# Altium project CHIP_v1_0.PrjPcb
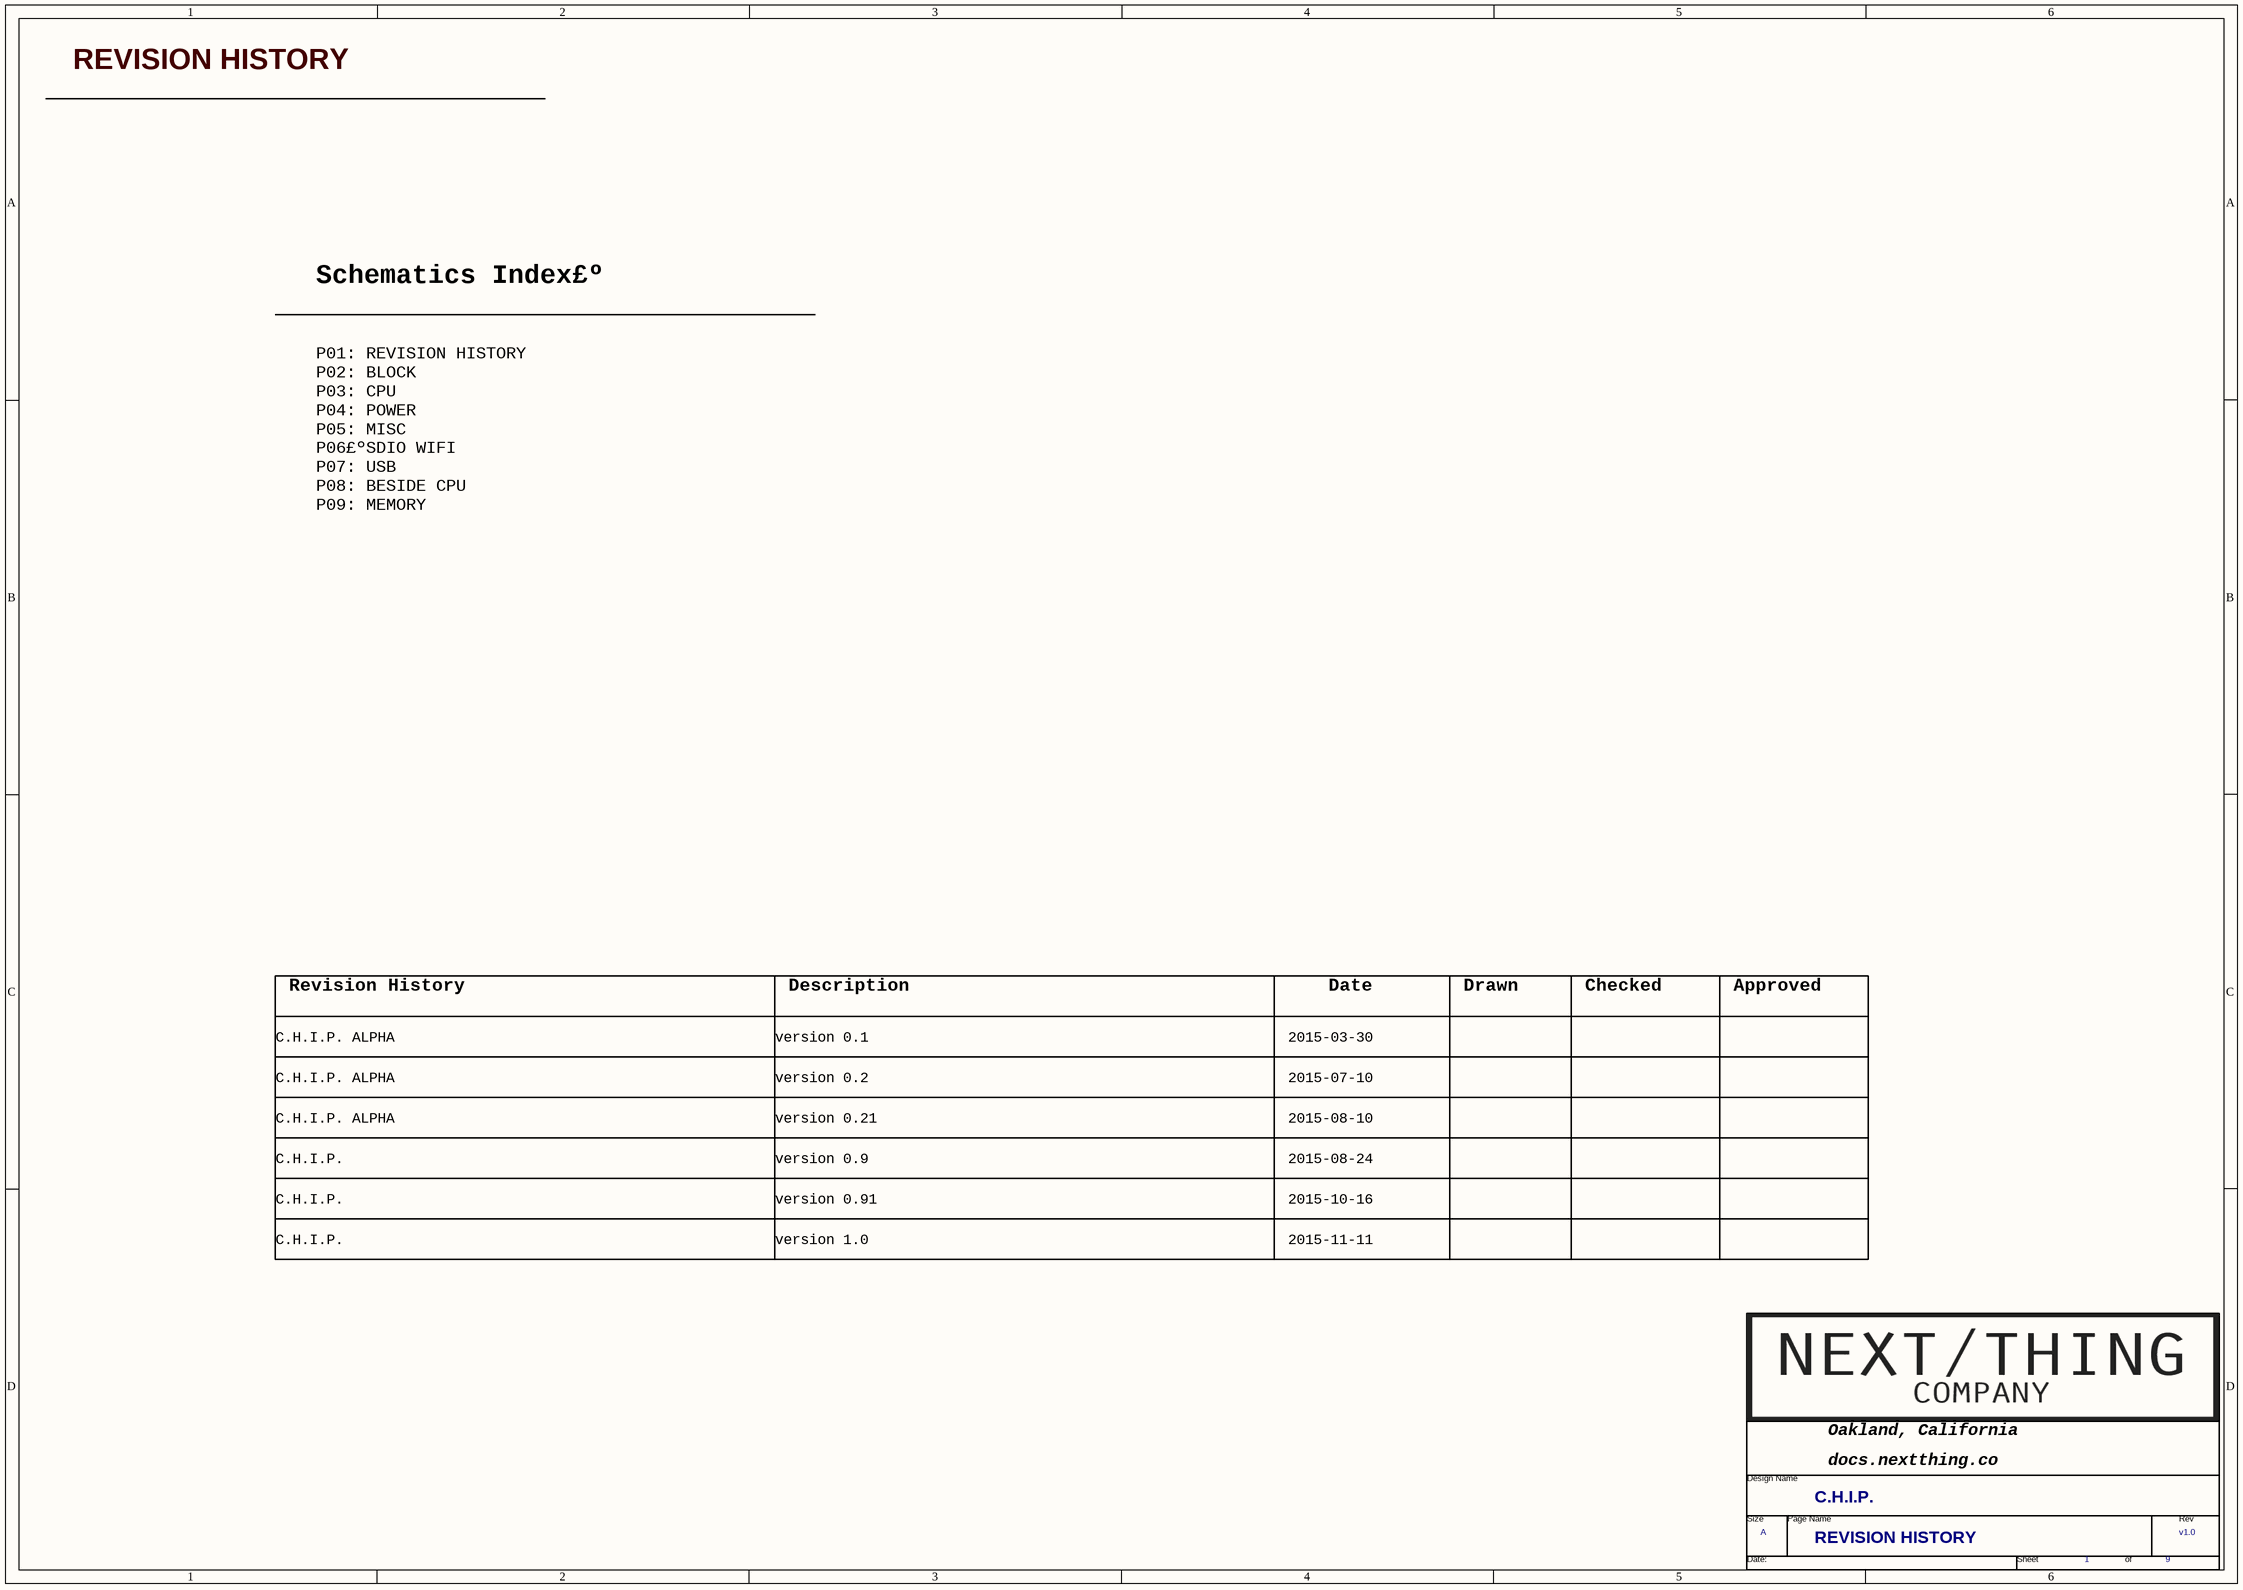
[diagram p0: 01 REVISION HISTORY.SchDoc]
9 sheets, 288 parts. Net scope: global (net labels, ports and power ports of the same name join across sheets).
Sheets:
  01 REVISION HISTORY.SchDoc
  02 BLOCK.SchDoc
  03 CPU.SchDoc
  04 POWER.SchDoc
  05 MISC.SchDoc
  06 SDIO WIFI&BT.SchDoc
  07 USB.SchDoc
  08 BESIDE CPU.SchDoc
  09 DDR3.SchDoc

## Sheet 01 REVISION HISTORY.SchDoc
size 420 x 297 mm

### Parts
(Parts that share a designator on the sheet are numbered #1, #2 ... from top to bottom, then left to right.)
*#1  Page Count: 9  Page Number: 1  Page Size: A  Title: C.H.I.P.  RevCode: v1.0  Doc: REVISION HISTORY  (hidden comment: TitleBlock1-nextthing)  (graphical)

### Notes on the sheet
- REVISION HISTORY
- Schematics Index£º
- P01: REVISION HISTORY
  P02: BLOCK
  P03: CPU
  P04: POWER
  P05: MISC
  P06£ºSDIO WIFI
  P07: USB
  P08: BESIDE CPU
  P09: MEMORY
- Revision History
- Description
- Date
- Drawn
- Checked
- Approved
- C.H.I.P. ALPHA
- version 0.1
- 2015-03-30
- version 0.2
- version 0.21
- 2015-07-10
- 2015-08-10
- C.H.I.P.
- version 0.9
- version 0.91
- 2015-08-24
- 2015-10-16
- version 1.0
- 2015-11-11

## Sheet 02 BLOCK.SchDoc
size 420 x 297 mm
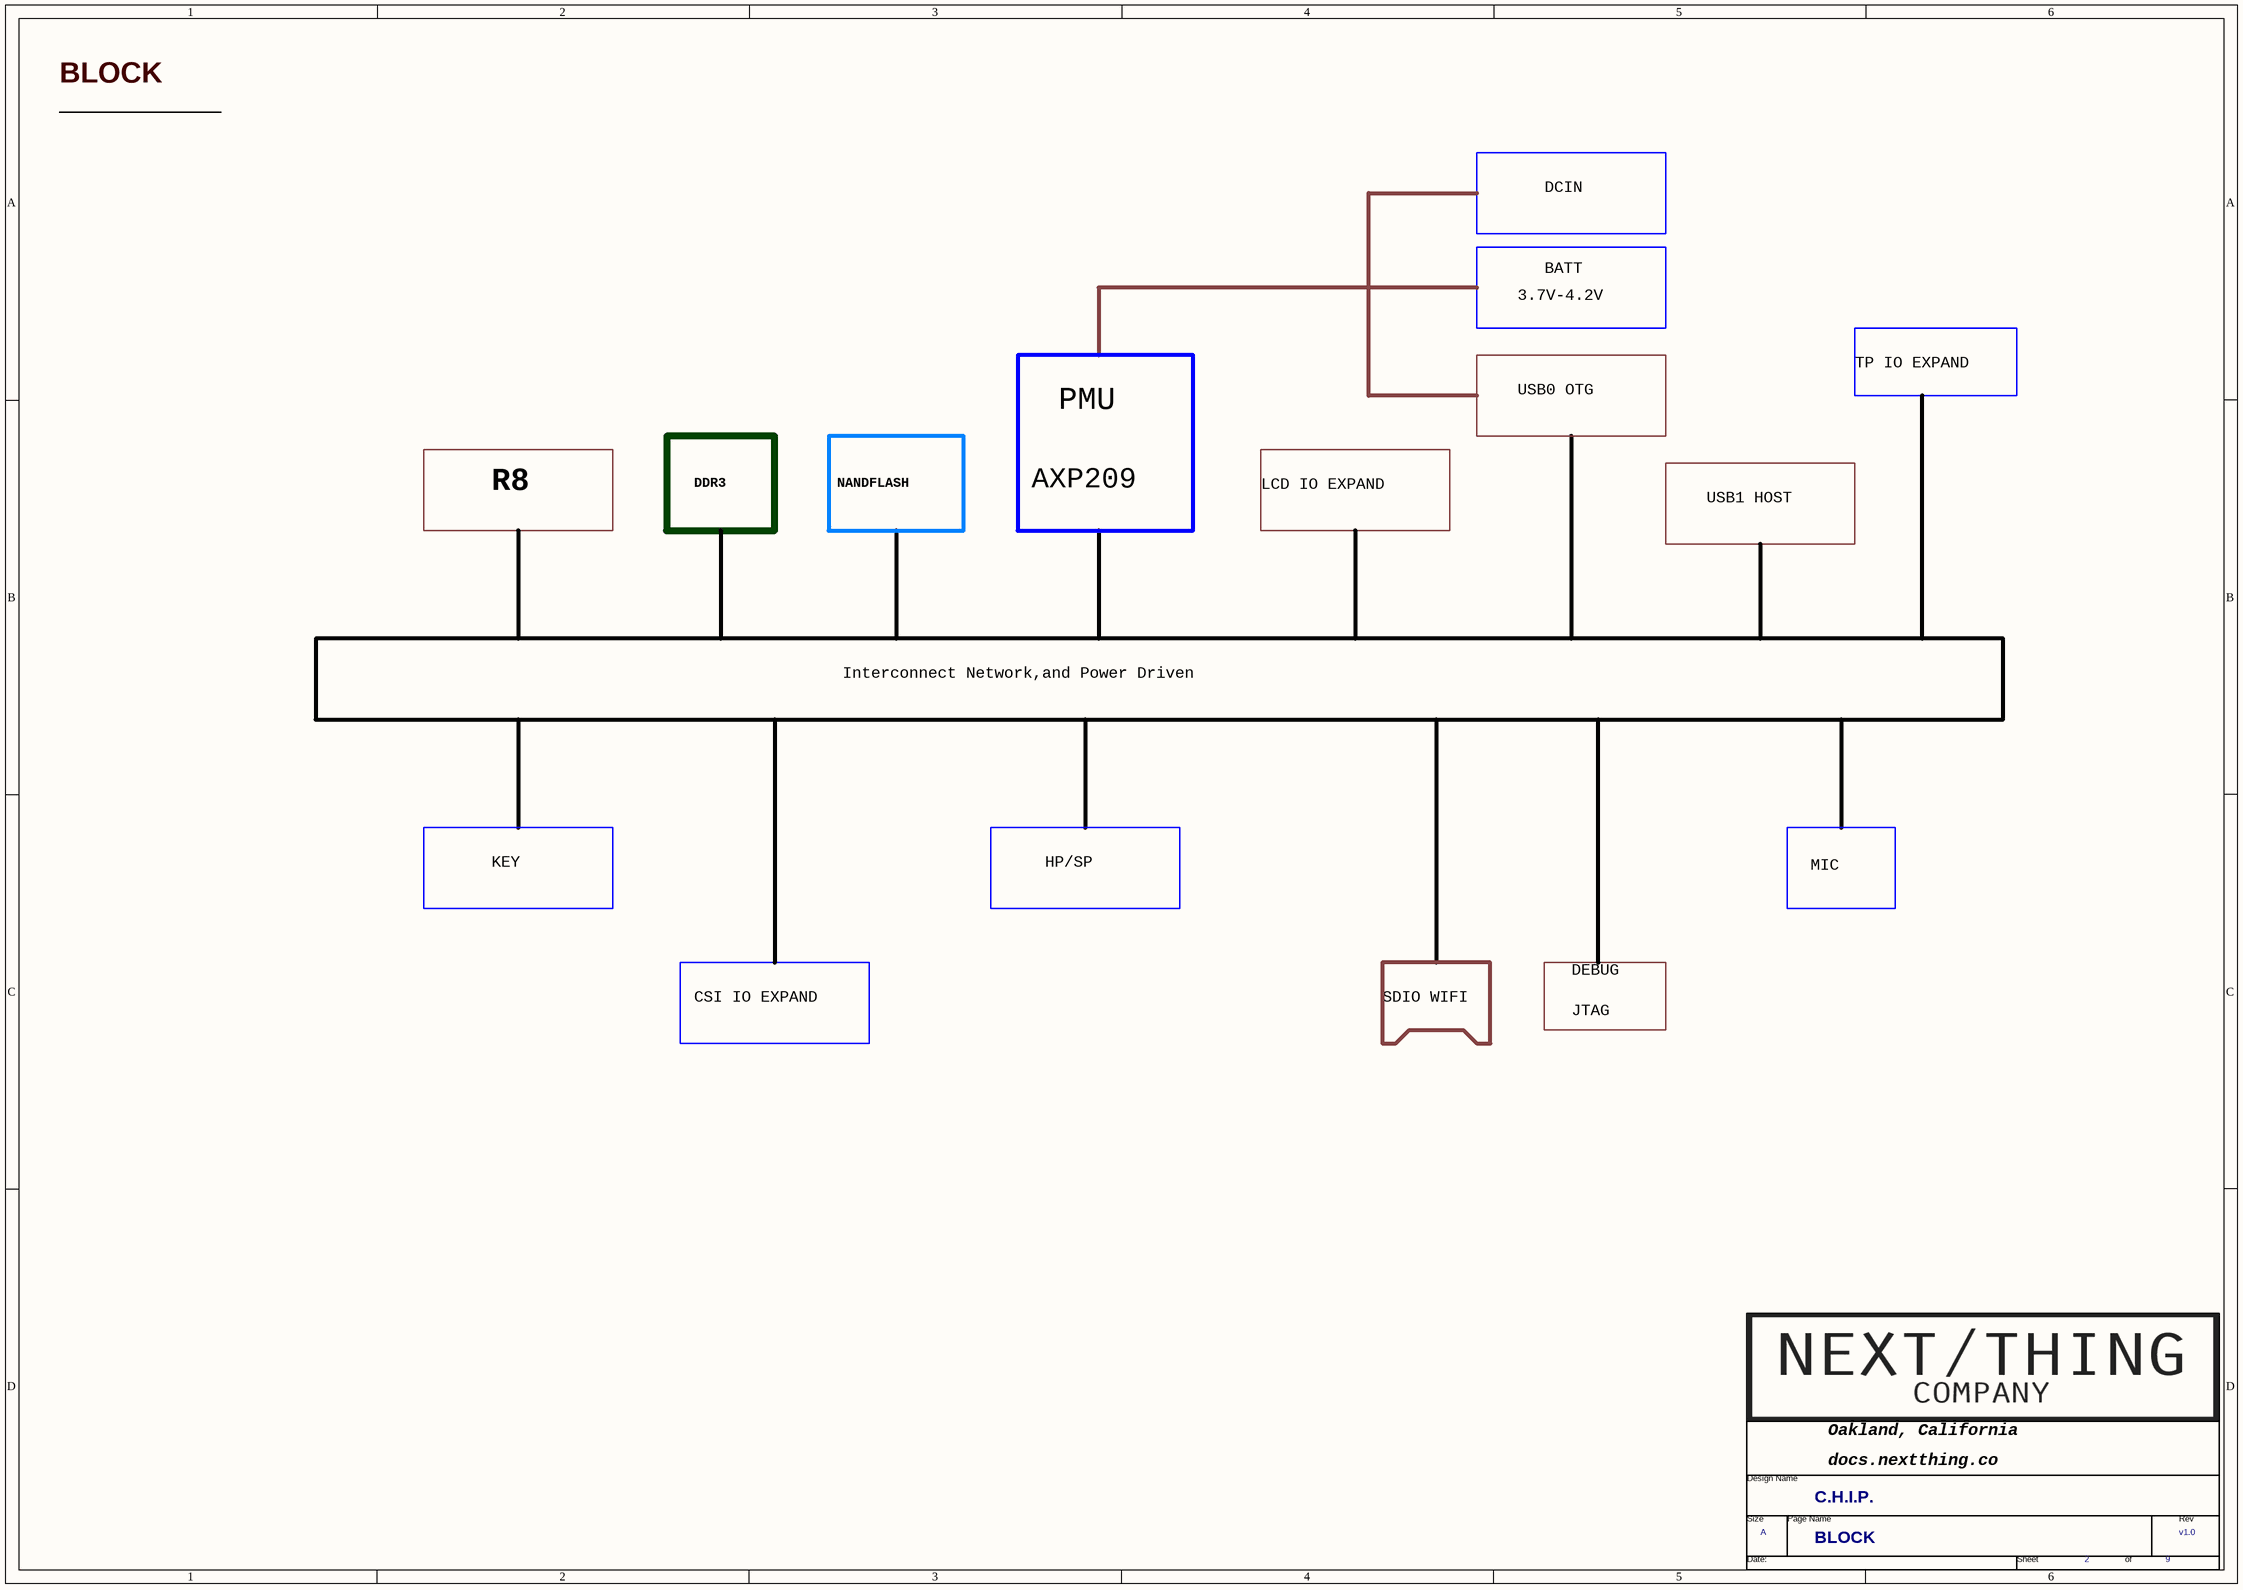
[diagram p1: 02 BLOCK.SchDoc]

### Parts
(Parts that share a designator on the sheet are numbered #1, #2 ... from top to bottom, then left to right.)
*#2  Page Count: 9  Page Number: 2  Page Size: A  Title: C.H.I.P.  RevCode: v1.0  Doc: BLOCK  (hidden comment: TitleBlock1-nextthing)  (graphical)

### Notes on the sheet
- BLOCK
- DCIN
- 3.7V-4.2V
- BATT
- USB0 OTG
- TP IO EXPAND
- PMU
- R8
- DDR3
- NANDFLASH
- AXP209
- LCD IO EXPAND
- USB1 HOST
- Interconnect Network,and Power Driven
- KEY
- HP/SP
- MIC
- CSI IO EXPAND
- SDIO WIFI
- DEBUG
- JTAG

## Sheet 03 CPU.SchDoc
size 420 x 297 mm
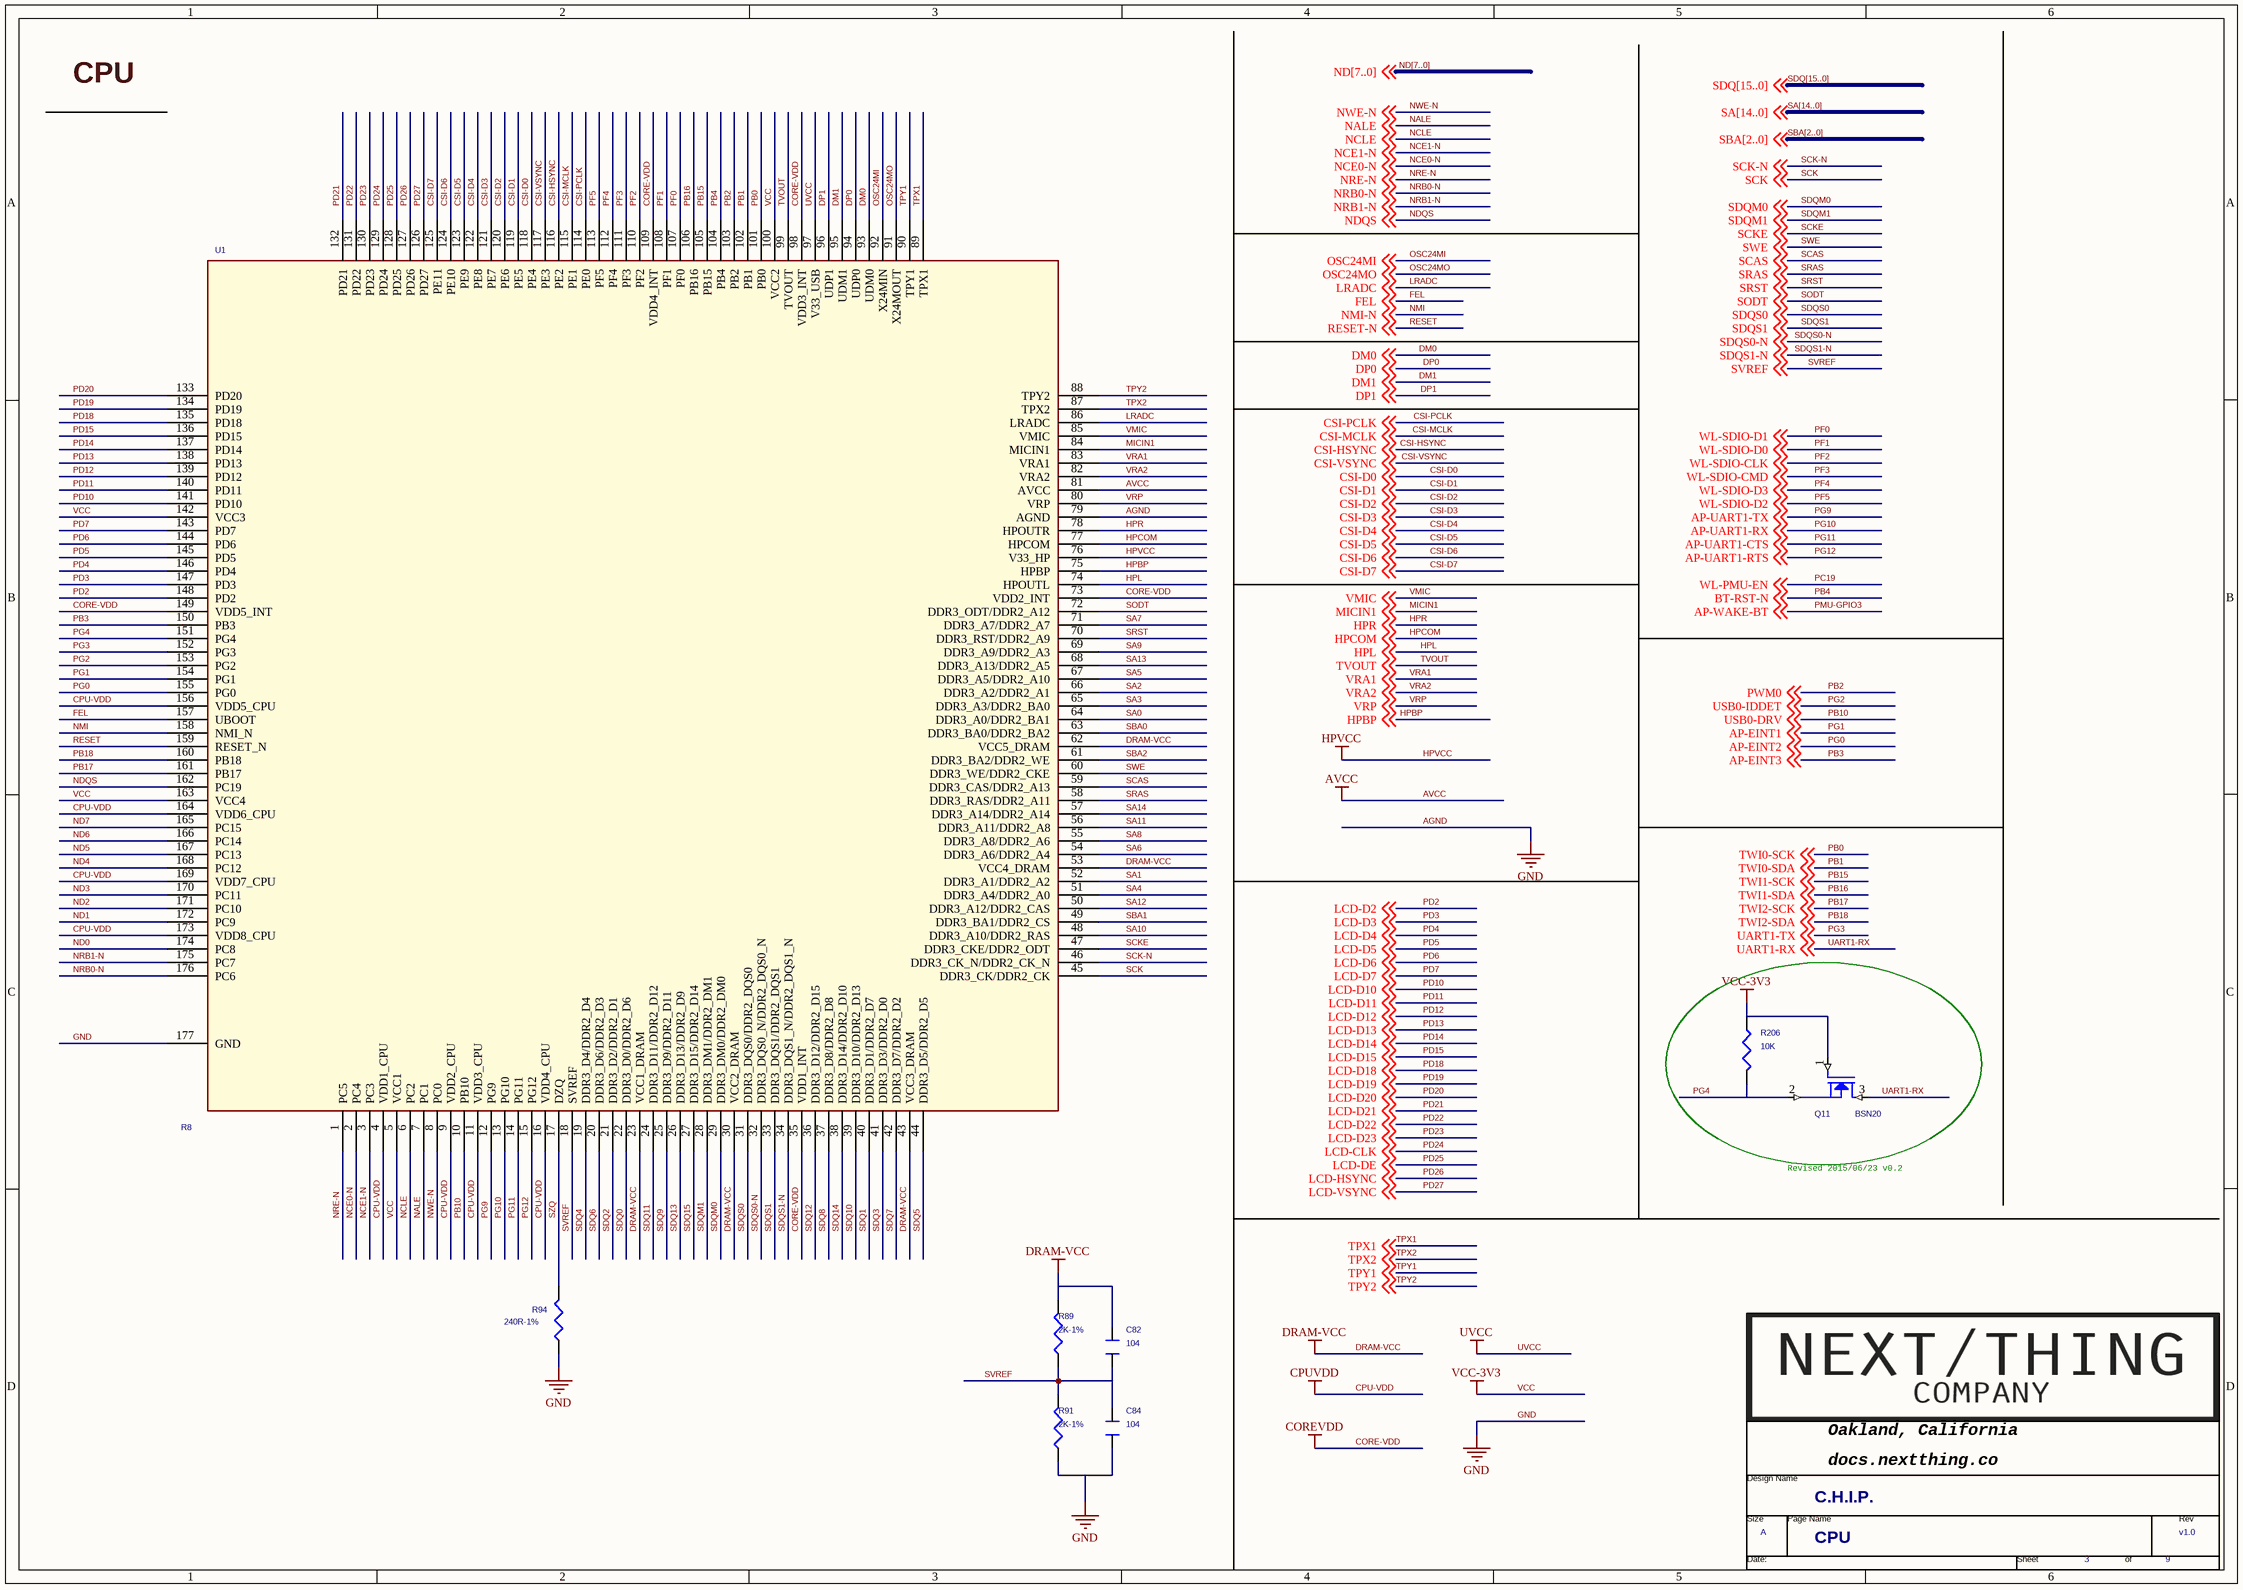
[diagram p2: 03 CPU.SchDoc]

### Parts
(Parts that share a designator on the sheet are numbered #1, #2 ... from top to bottom, then left to right.)
*#3  Page Count: 9  Page Number: 3  Page Size: A  Title: C.H.I.P.  RevCode: v1.0  Doc: CPU  (hidden comment: TitleBlock1-nextthing)  (graphical)
C82  104  [0805]
C84  104  [0805]
Q11  BSN20  [sot-23]
R89  2K-1%  [0805]
R91  2K-1%  [0805]
R94  240R-1%  [C0201]
R206  10K  [0805]
U1  R8  [TQFP177P0_4]

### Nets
AGND: C84.2 R91.1 R94.1 U1.79(AGND) U1.177(GND)  [also labelled GND]
AVCC: U1.81(AVCC)
CORE-VDD: U1.35(VDD1_INT) U1.73(VDD2_INT) U1.98(VDD3_INT) U1.109(VDD4_INT) U1.149(VDD5_INT)  [also labelled COREVDD]
CPU-VDD: U1.4(VDD1_CPU) U1.9(VDD2_CPU) U1.11(VDD3_CPU) U1.16(VDD4_CPU) U1.156(VDD5_CPU) U1.164(VDD6_CPU) U1.169(VDD7_CPU) U1.173(VDD8_CPU)  [also labelled CPUVDD]  [project net CPU-1V2]
DRAM-VCC: C82.1 R89.2 U1.23(VCC1_DRAM) U1.30(VCC2_DRAM) U1.43(VCC3_DRAM) U1.53(VCC4_DRAM) U1.62(VCC5_DRAM)
HPVCC: Q11.1(GATE) R206.1 U1.5(VCC1) U1.76(V33_HP) U1.97(V33_USB) U1.100(VCC2) U1.142(VCC3) U1.163(VCC4)  [also labelled UVCC, VCC, VCC-3V3]
AP-EINT1: U1.154(PG1) ; off-sheet AP-EINT1  [also labelled PG1]
AP-EINT2: U1.155(PG0) ; off-sheet AP-EINT2  [also labelled PG0]
AP-EINT3: U1.150(PB3) ; off-sheet AP-EINT3  [also labelled PB3]
AP-UART1-CTS: U1.14(PG11) ; off-sheet AP-UART1-CTS  [also labelled PG11]  [project net BT-UART-RTS]
AP-UART1-RTS: U1.15(PG12) ; off-sheet AP-UART1-RTS  [also labelled PG12]  [project net BT-UART-CTS]
AP-UART1-RX: U1.13(PG10) ; off-sheet AP-UART1-RX  [also labelled PG10]  [project net BT-UART-TX]
AP-UART1-TX: U1.12(PG9) ; off-sheet AP-UART1-TX  [also labelled PG9]  [project net BT-UART-RX]
BT-RST-N: U1.104(PB4) ; off-sheet BT-RST-N  [also labelled PB4]
CSI-D0: U1.118(PE4) ; off-sheet CSI-D0
CSI-D1: U1.119(PE5) ; off-sheet CSI-D1
CSI-D2: U1.120(PE6) ; off-sheet CSI-D2
CSI-D3: U1.121(PE7) ; off-sheet CSI-D3
CSI-D4: U1.122(PE8) ; off-sheet CSI-D4
CSI-D5: U1.123(PE9) ; off-sheet CSI-D5
CSI-D6: U1.124(PE10) ; off-sheet CSI-D6
CSI-D7: U1.125(PE11) ; off-sheet CSI-D7
CSI-HSYNC: U1.116(PE2) ; off-sheet CSI-HSYNC
CSI-MCLK: U1.115(PE1) ; off-sheet CSI-MCLK
CSI-PCLK: U1.114(PE0) ; off-sheet CSI-PCLK
CSI-VSYNC: U1.117(PE3) ; off-sheet CSI-VSYNC
DM0: U1.93(UDM0) ; off-sheet DM0
DM1: U1.95(UDM1) ; off-sheet DM1
DP0: U1.94(UDP0) ; off-sheet DP0
DP1: U1.96(UDP1) ; off-sheet DP1
FEL: U1.157(UBOOT) ; off-sheet FEL
HPBP: U1.75(HPBP) ; off-sheet HPBP
HPCOM: U1.77(HPCOM) ; off-sheet HPCOM
HPL: U1.74(HPOUTL) ; off-sheet HPL
HPR: U1.78(HPOUTR) ; off-sheet HPR
LCD-CLK: U1.129(PD24) ; off-sheet LCD-CLK  [also labelled PD24]
LCD-D2: U1.148(PD2) ; off-sheet LCD-D2  [also labelled PD2]
LCD-D3: U1.147(PD3) ; off-sheet LCD-D3  [also labelled PD3]
LCD-D4: U1.146(PD4) ; off-sheet LCD-D4  [also labelled PD4]
LCD-D5: U1.145(PD5) ; off-sheet LCD-D5  [also labelled PD5]
LCD-D6: U1.144(PD6) ; off-sheet LCD-D6  [also labelled PD6]
LCD-D7: U1.143(PD7) ; off-sheet LCD-D7  [also labelled PD7]
LCD-D10: U1.141(PD10) ; off-sheet LCD-D10  [also labelled PD10]
LCD-D11: U1.140(PD11) ; off-sheet LCD-D11  [also labelled PD11]
LCD-D12: U1.139(PD12) ; off-sheet LCD-D12  [also labelled PD12]
LCD-D13: U1.138(PD13) ; off-sheet LCD-D13  [also labelled PD13]
LCD-D14: U1.137(PD14) ; off-sheet LCD-D14  [also labelled PD14]
LCD-D15: U1.136(PD15) ; off-sheet LCD-D15  [also labelled PD15]
LCD-D18: U1.135(PD18) ; off-sheet LCD-D18  [also labelled PD18]
LCD-D19: U1.134(PD19) ; off-sheet LCD-D19  [also labelled PD19]
LCD-D20: U1.133(PD20) ; off-sheet LCD-D20  [also labelled PD20]
LCD-D21: U1.132(PD21) ; off-sheet LCD-D21  [also labelled PD21]
LCD-D22: U1.131(PD22) ; off-sheet LCD-D22  [also labelled PD22]
LCD-D23: U1.130(PD23) ; off-sheet LCD-D23  [also labelled PD23]
LCD-DE: U1.128(PD25) ; off-sheet LCD-DE  [also labelled PD25]
LCD-HSYNC: U1.127(PD26) ; off-sheet LCD-HSYNC  [also labelled PD26]
LCD-VSYNC: U1.126(PD27) ; off-sheet LCD-VSYNC  [also labelled PD27]
LRADC: U1.86(LRADC) ; off-sheet LRADC
MICIN1: U1.84(MICIN1) ; off-sheet MICIN1
NALE: U1.7(PC1) ; off-sheet NALE
NCE0-N: U1.2(PC4) ; off-sheet NCE0-N
NCE1-N: U1.3(PC3) ; off-sheet NCE1-N
NCLE: U1.6(PC2) ; off-sheet NCLE
ND0: U1.174(PC8)
ND1: U1.172(PC9)
ND2: U1.171(PC10)
ND3: U1.170(PC11)
ND4: U1.168(PC12)
ND5: U1.167(PC13)
ND6: U1.166(PC14)
ND7: U1.165(PC15)
NDQS: U1.162(PC19) ; off-sheet NDQS
NMI: U1.158(NMI_N) ; off-sheet NMI-N  [also labelled NMI-N]
NRB0-N: U1.176(PC6) ; off-sheet NRB0-N
NRB1-N: U1.175(PC7) ; off-sheet NRB1-N
NRE-N: U1.1(PC5) ; off-sheet NRE-N
NWE-N: U1.8(PC0) ; off-sheet NWE-N
OSC24MI: U1.92(X24MIN) ; off-sheet OSC24MI
OSC24MO: U1.91(X24MOUT) ; off-sheet OSC24MO
PB0: U1.101(PB0) ; off-sheet TWI0-SCK  [also labelled TWI0-SCK]
PB1: U1.102(PB1) ; off-sheet TWI0-SDA  [also labelled TWI0-SDA]
PB2: U1.103(PB2) ; off-sheet PWM0  [also labelled PWM0]
PB10: U1.10(PB10) ; off-sheet USB0-DRV  [also labelled USB0-DRV]
PB15: U1.105(PB15) ; off-sheet TWI1-SCK  [also labelled TWI1-SCK]
PB16: U1.106(PB16) ; off-sheet TWI1-SDA  [also labelled TWI1-SDA]
PB17: U1.161(PB17) ; off-sheet TWI2-SCK  [also labelled TWI2-SCK]
PB18: U1.160(PB18) ; off-sheet TWI2-SDA  [also labelled TWI2-SDA]
PF0: U1.107(PF0) ; off-sheet WL-SDIO-D1  [also labelled WL-SDIO-D1]
PF1: U1.108(PF1) ; off-sheet WL-SDIO-D0  [also labelled WL-SDIO-D0]
PF2: U1.110(PF2) ; off-sheet WL-SDIO-CLK  [also labelled WL-SDIO-CLK]
PF3: U1.111(PF3) ; off-sheet WL-SDIO-CMD  [also labelled WL-SDIO-CMD]
PF4: U1.112(PF4) ; off-sheet WL-SDIO-D3  [also labelled WL-SDIO-D3]
PF5: U1.113(PF5) ; off-sheet WL-SDIO-D2  [also labelled WL-SDIO-D2]
PG2: U1.153(PG2) ; off-sheet USB0-IDDET  [also labelled USB0-IDDET]
PG3: U1.152(PG3) ; off-sheet UART1-TX  [also labelled UART1-TX]
PG4: Q11.2(SOURCE) R206.2 U1.151(PG4)
RESET: U1.159(RESET_N) ; off-sheet RESET-N  [also labelled RESET-N]
SA0: U1.64(DDR3_A0/DDR2_BA1)
SA1: U1.52(DDR3_A1/DDR2_A2)
SA2: U1.66(DDR3_A2/DDR2_A1)
SA3: U1.65(DDR3_A3/DDR2_BA0)
SA4: U1.51(DDR3_A4/DDR2_A0)
SA5: U1.67(DDR3_A5/DDR2_A10)
SA6: U1.54(DDR3_A6/DDR2_A4)
SA7: U1.71(DDR3_A7/DDR2_A7)
SA8: U1.55(DDR3_A8/DDR2_A6)
SA9: U1.69(DDR3_A9/DDR2_A3)
SA10: U1.48(DDR3_A10/DDR2_RAS)
SA11: U1.56(DDR3_A11/DDR2_A8)
SA12: U1.50(DDR3_A12/DDR2_CAS)
SA13: U1.68(DDR3_A13/DDR2_A5)
SA14: U1.57(DDR3_A14/DDR2_A14)
SBA0: U1.63(DDR3_BA0/DDR2_BA2)
SBA1: U1.49(DDR3_BA1/DDR2_CS)
SBA2: U1.61(DDR3_BA2/DDR2_WE)
SCAS: U1.59(DDR3_CAS/DDR2_A13) ; off-sheet SCAS
SCK: U1.45(DDR3_CK/DDR2_CK) ; off-sheet SCK
SCK-N: U1.46(DDR3_CK_N/DDR2_CK_N) ; off-sheet SCK-N
SCKE: U1.47(DDR3_CKE/DDR2_ODT) ; off-sheet SCKE
SDQ0: U1.22(DDR3_D0/DDR2_D6)
SDQ1: U1.40(DDR3_D1/DDR2_D7)
SDQ2: U1.21(DDR3_D2/DDR2_D1)
SDQ3: U1.41(DDR3_D3/DDR2_D0)
SDQ4: U1.19(DDR3_D4/DDR2_D4)
SDQ5: U1.44(DDR3_D5/DDR2_D5)
SDQ6: U1.20(DDR3_D6/DDR2_D3)
SDQ7: U1.42(DDR3_D7/DDR2_D2)
SDQ8: U1.37(DDR3_D8/DDR2_D8)
SDQ9: U1.25(DDR3_D9/DDR2_D11)
SDQ10: U1.39(DDR3_D10/DDR2_D13)
SDQ11: U1.24(DDR3_D11/DDR2_D12)
SDQ12: U1.36(DDR3_D12/DDR2_D15)
SDQ13: U1.26(DDR3_D13/DDR2_D9)
SDQ14: U1.38(DDR3_D14/DDR2_D10)
SDQ15: U1.27(DDR3_D15/DDR2_D14)
SDQM0: U1.29(DDR3_DM0/DDR2_DM0) ; off-sheet SDQM0
SDQM1: U1.28(DDR3_DM1/DDR2_DM1) ; off-sheet SDQM1
SDQS0: U1.31(DDR3_DQS0/DDR2_DQS0) ; off-sheet SDQS0
SDQS0-N: U1.32(DDR3_DQS0_N/DDR2_DQS0_N) ; off-sheet SDQS0-N
SDQS1: U1.33(DDR3_DQS1/DDR2_DQS1) ; off-sheet SDQS1
SDQS1-N: U1.34(DDR3_DQS1_N/DDR2_DQS1_N) ; off-sheet SDQS1-N
SODT: U1.72(DDR3_ODT/DDR2_A12) ; off-sheet SODT
SRAS: U1.58(DDR3_RAS/DDR2_A11) ; off-sheet SRAS
SRST: U1.70(DDR3_RST/DDR2_A9) ; off-sheet SRST
SVREF: C82.2 C84.1 R89.1 R91.2 U1.18(SVREF) ; off-sheet SVREF
SWE: U1.60(DDR3_WE/DDR2_CKE) ; off-sheet SWE
SZQ: R94.2 U1.17(DZQ)
TPX1: U1.89(TPX1) ; off-sheet TPX1
TPX2: U1.87(TPX2) ; off-sheet TPX2
TPY1: U1.90(TPY1) ; off-sheet TPY1
TPY2: U1.88(TPY2) ; off-sheet TPY2
TVOUT: U1.99(TVOUT) ; off-sheet TVOUT
UART1-RX: Q11.3(DRAIN) ; off-sheet UART1-RX
VMIC: U1.85(VMIC) ; off-sheet VMIC
VRA1: U1.83(VRA1) ; off-sheet VRA1
VRA2: U1.82(VRA2) ; off-sheet VRA2
VRP: U1.80(VRP) ; off-sheet VRP

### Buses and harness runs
bus ND[7..0]
bus SA[14..0]
bus SBA[2..0]
bus SDQ[15..0]

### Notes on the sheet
- CPU
- Revised 2015/06/23 v0.2

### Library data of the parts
C82 C84 = CAP_0
Q11 = NMOS_xp151_SOT23
R89 R91 = R1 0805
R94 = R_Dup2
R206 = R1_0805: ROOM: DRAM
U1 = AW1625_CSI_eLQFP176_3

## Sheet 04 POWER.SchDoc
size 420 x 297 mm
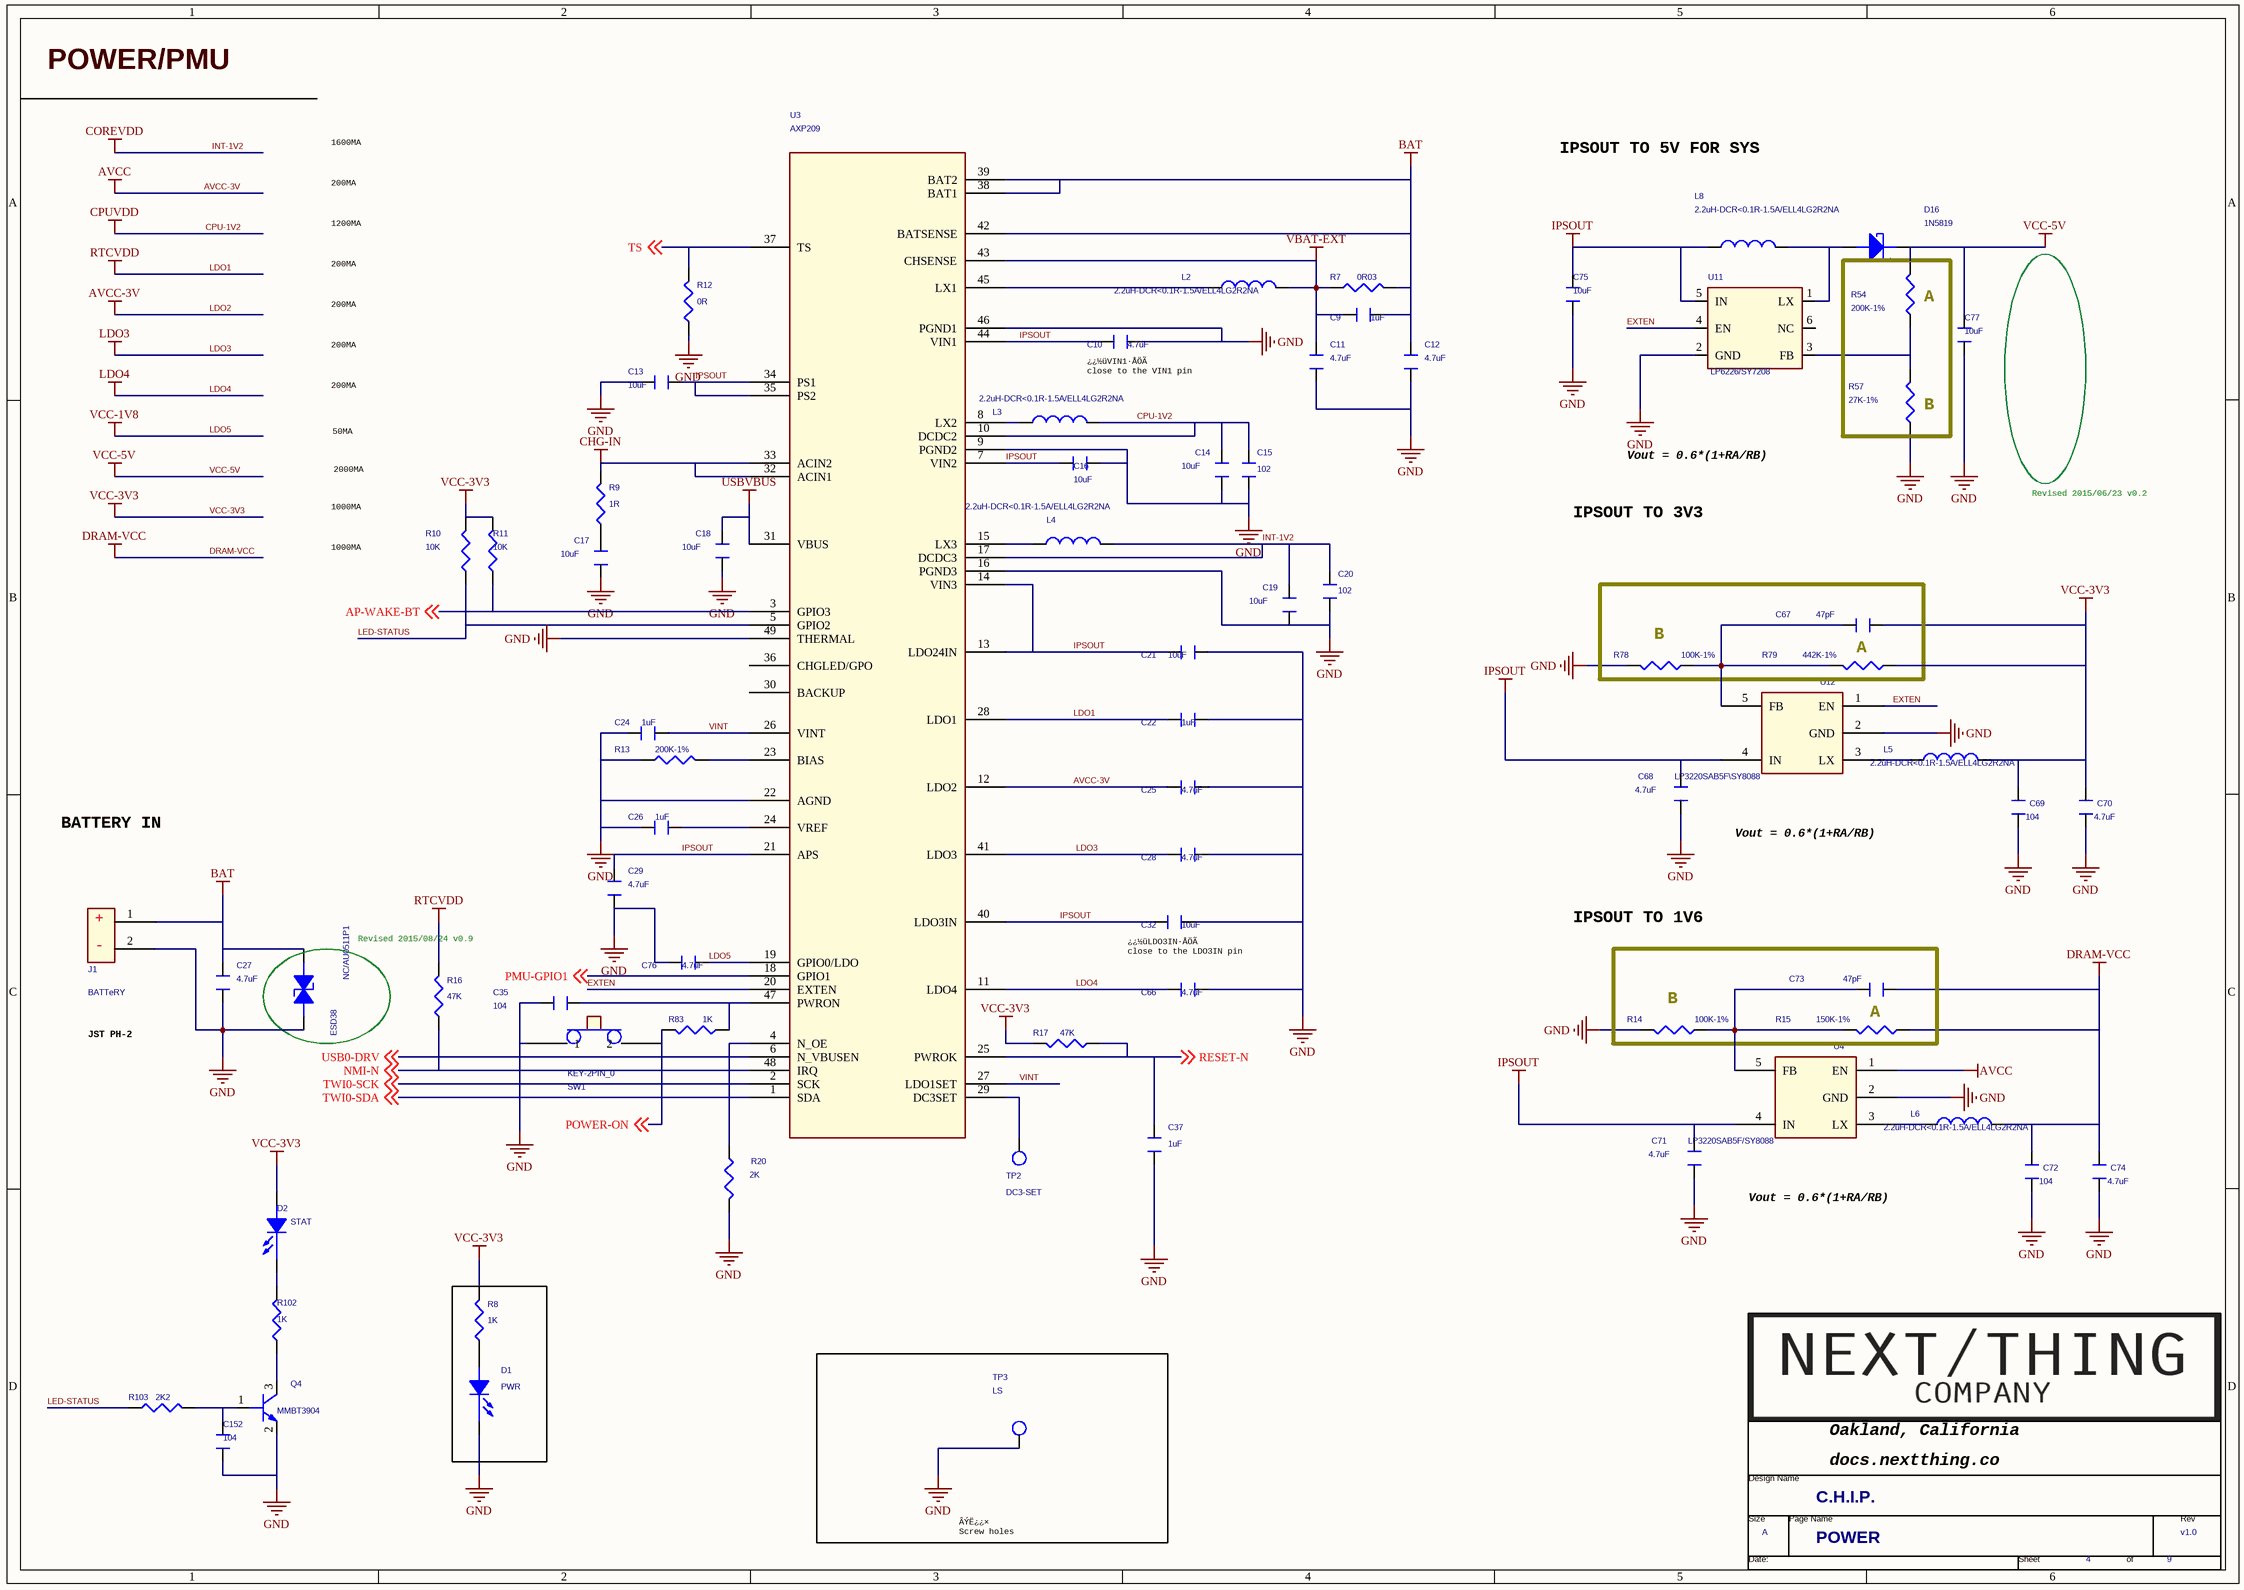
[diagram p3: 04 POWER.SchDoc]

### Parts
(Parts that share a designator on the sheet are numbered #1, #2 ... from top to bottom, then left to right.)
*#4  Page Count: 9  Page Number: 4  Page Size: A  Title: C.H.I.P.  RevCode: v1.0  Doc: POWER  (hidden comment: TitleBlock1-nextthing)  (graphical)
C9  1uF  [CC0402]
C10  4.7uF  [Cc0603]
C11  4.7uF  [CC0603]
C12  4.7uF  [CC0603]
C13  10uF  [CC0603]
C14  10uF  [CC0603]
C15  102  [CC0402]
C16  10uF  [CC0603]
C17  10uF  [CC0603]
C18  10uF  [CC0603]
C19  10uF  [CC0603]
C20  102  [C0201]
C21  10uF  [CC0603]
C22  1uF  [CC0402]
C24  1uF  [CC0402]
C25  4.7uF  [CC0603]
C26  1uF  [CC0402]
C27  4.7uF  [CC0603]
C28  4.7uF  [CC0603]
C29  4.7uF  [CC0603]
C32  10uF  [CC0603]
C35  104  [C0201]
C37  1uF  [CC0402]
C66  4.7uF  [CC0603]
C67  47pF  [C0201]
C68  4.7uF  [CC0603]
C69  104  [C0201]
C70  4.7uF  [CC0603]
C71  4.7uF  [CC0603]
C72  104  [C0201]
C73  47pF  [C0201]
C74  4.7uF  [CC0603]
C75  10uF  [CC0603]
C76  4.7uF  [CC0603]
C77  10uF  [CC0603]
C152  104  [C0201]
D1  PWR  [D0603]
D2  STAT  [D0603]
D16  1N5819  [SOD123]
ESD38  NC/AU0511P1  [R0402]
J1  BATTeRY  [CON2-PT2-6X6H4_7B]
L2  2.2uH-DCR<0.1R-1.5A/ELL4LG2R2NA  [L3518]
L3  2.2uH-DCR<0.1R-1.5A/ELL4LG2R2NA  [L3518]
L4  2.2uH-DCR<0.1R-1.5A/ELL4LG2R2NA  [L3518]
L5  2.2uH-DCR<0.1R-1.5A/ELL4LG2R2NA  [L3518]
L6  2.2uH-DCR<0.1R-1.5A/ELL4LG2R2NA  [L3518]
L8  2.2uH-DCR<0.1R-1.5A/ELL4LG2R2NA  [L3518]
Q4  MMBT3904  [SOT-23]
R7  0R03  [R0805]
R8  1K  [C0201]
R9  1R  [R0402]
R10  10K  [C0201]
R11  10K  [C0201]
R12  0R  [C0201]
R13  200K-1%  [C0201]
R14  100K-1%  [R0402]
R15  150K-1%  [R0402]
R16  47K  [C0201]
R17  47K  [C0201]
R20  2K  [C0201]
R54  200K-1%  [C0201]
R57  27K-1%  [C0201]
R78  100K-1%  [R0402]
R79  442K-1%  [R0402]
R83  1K  [C0201]
R102  1K  [C0201]
R103  2K2  [C0201]
SW1  KEY-2PIN_0  [KEY-2]
TP2  DC3-SET  [TP40_SMD]
TP3  LS  [PAD5_5D3]
U3  AXP209  [QFN49_0_4H0_8A]
U4  LP3220SAB5F/SY8088  [TSOT-23-6]
U11  LP6226/SY7208  [SOT23-6]
U12  LP3220SAB5F\SY8088  [TSOT-23-6]

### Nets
AVCC: C25.1 U3.12(LDO2) U4.1(EN)  [also labelled AVCC-3V, LDO2]
BAT: C9.2 C12.1 C27.2 ESD38.1(ANODE) J1.1 R7.1 U3.38(BAT1) U3.39(BAT2) U3.42(BATSENSE)
CHG-IN: R9.2 U3.32(ACIN1) U3.33(ACIN2)
COREVDD: C19.1 C20.1 L4.1 U3.17(DCDC3)  [also labelled INT-1V2]  [project net CORE-VDD]
CPU-1V2: C14.1 C15.1 L3.1 U3.10(DCDC2)  [also labelled CPUVDD]
DRAM-VCC: C72.1 C73.1 C74.1 L6.1 R15.2
GND: C10.2 C11.2 C12.2 C13.1 C14.2 C15.2 C16.2 C17.2 C18.2 C19.2 C20.2 C21.2 C22.1 C24.2 C25.2 C26.1 C27.1 C28.1 C29.2 C32.2 C35.1 C37.1 C66.1 C68.2 C69.2 C70.2 C71.2 C72.2 C74.2 C75.2 C76.2 C77.2 C152.1 D1.2(CATHODE) ESD38.2(CATHODE) J1.2 Q4.2(E) R12.1 R13.1 R14.1 R20.2 R57.1 R78.1 SW1.1 TP3.1(TP) U3.9(PGND2) U3.16(PGND3) U3.22(AGND) U3.46(PGND1) U3.49(THERMAL) U4.2(GND) U11.2(GND) U12.2(GND)  [project net AGND]
IPSOUT: C10.1 C13.2 C16.1 C21.1 C29.1 C32.1 C68.1 C71.1 C75.1 L8.1 U3.7(VIN2) U3.13(LDO24IN) U3.14(VIN3) U3.21(APS) U3.34(PS1) U3.35(PS2) U3.40(LDO3IN) U3.44(VIN1) U4.4(IN) U11.5(IN) U12.4(IN)
LDO1: C22.2 R16.2 U3.28(LDO1)  [also labelled RTCVDD]
LDO3: C28.2 C66.2 U3.11(LDO4) U3.41(LDO3)  [also labelled LDO4]
LDO5: C76.1 U3.19(GPIO0/LDO)  [also labelled VCC-1V8]
USBVBUS: C18.1 U3.31(VBUS)
VBAT-EXT: C9.1 C11.1 L2.1 R7.2 U3.43(CHSENSE)
VCC-3V3: C67.1 C69.1 C70.1 D2.1(ANODE) L5.1 R8.2 R10.2 R11.2 R17.2 R79.2  [project net HPVCC]
VCC-5V: C77.1 D16.2 R54.2
AP-WAKE-BT: R11.1 U3.3(GPIO3) ; off-sheet AP-WAKE-BT
EXTEN: U3.20(EXTEN) U11.4(EN) U12.1(EN)
LED-STATUS: R10.1 R103.2 U3.5(GPIO2)
NMI-N: R16.1 U3.48(IRQ) ; off-sheet NMI-N  [project net NMI]
PMU-GPIO1: U3.18(GPIO1) ; off-sheet PMU-GPIO1
POWER-ON: R83.2 SW1.2 ; off-sheet POWER-ON
RESET-N: C37.2 R17.1 U3.25(PWROK) ; off-sheet RESET-N  [project net RESET]
TS: R12.2 U3.37(TS) ; off-sheet TS
TWI0-SCK: U3.2(SCK) ; off-sheet TWI0-SCK  [project net PB0]
TWI0-SDA: U3.1(SDA) ; off-sheet TWI0-SDA  [project net PB1]
USB0-DRV: U3.6(N_VBUSEN) ; off-sheet USB0-DRV  [project net PB10]
VINT: C24.1 U3.26(VINT) U3.27(LDO1SET)
NetC17_1: C17.1 R9.1
NetC26_2: C26.2 U3.24(VREF)
NetC35_2: C35.2 R83.1 U3.47(PWRON)
NetC67_2: C67.2 R78.2 R79.1 U12.5(FB)
NetC73_2: C73.2 R14.2 R15.1 U4.5(FB)
NetC152_2: C152.2 Q4.1(B) R103.1
NetD1_1: D1.1(ANODE) R8.1
NetD2_2: D2.2(CATHODE) R102.1
NetD16_1: D16.1 L8.2 U11.1(LX)
NetL2_2: L2.2 U3.45(LX1)
NetL3_2: L3.2 U3.8(LX2)
NetL4_2: L4.2 U3.15(LX3)
NetL5_2: L5.2 U12.3(LX)
NetL6_2: L6.2 U4.3(LX)
NetQ4_3: Q4.3(C) R102.2
NetR13_2: R13.2 U3.23(BIAS)
NetR20_1: R20.1 U3.4(N_OE)
NetR54_1: R54.1 R57.2 U11.3(FB)
NetTP2_1: TP2.1(TP) U3.29(DC3SET)

Not connected (* = marked no-connect by the designer): U3 30(BACKUP) 36(CHGLED/GPO); U11 6(NC)

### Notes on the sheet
- POWER/PMU
- 200MA
- 1600MA
- IPSOUT TO 5V FOR SYS
- 1200MA
- (near R54) A
- (near C10) ¿¿½üVIN1·ÅÖÃ
  close to the VIN1 pin
- 50MA
- Vout = 0.6*(1+RA/RB)
- (near R57) B
- 1000MA
- 2000MA
- IPSOUT TO 3V3
- Revised 2015/06/23 v0.2
- (near R78) B
- A
- BATTERY IN
- (near J1) +
- (near C32) ¿¿½üLDO3IN·ÅÖÃ
  close to the LDO3IN pin
- IPSOUT TO 1V6
- (near J1) -
- (near R16) Revised 2015/08/24 v0.9
- (near R14) B
- JST PH-2
- ÂÝË¿¿×
  Screw holes

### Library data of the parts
C9-C14 C16-C19 C21 C22 C24-C26 C28 C29 C32 C35 C37 C66 C76 = CAPACITOR_0_Dup2: PAGE: 1
C15 C20 = CAPACITOR_1: PAGE: 1
C27 = CAPACITOR_0_Dup4: PAGE: 1
C67-C75 C77 = CAPACITOR_0_Dup1: PAGE: 1
C152 = CAPACITOR_0_Dup4: PAGE: 3; ROOM: MODEM
D1 = LED_0: PAGE: 1
D2 = LED_0: ROOM: MODEM; PAGE: 1
D16 = DIODE_SCHOTTKY_0
ESD38 = 1_1.5KE100A: 1ST PART DESCRIPTION: WILL ESD9B5V Bidirection ESD Protection
J1 = CON3_0
L2-L4 L8 = INDUCTOR_1_Dup1
L5 L6 = INDUCTOR_0
Q4 = NPN: ROOM: MODEM
R7 = R: PAGE: 1
R8-R13 R16 R17 R20 R83 = R_Dup1
R14 R15 R78 R79 = ?_0_Dup1
R54 R57 = R_Dup2
R102 R103 = RESISTOR_Dup1: ROOM: MODEM
TP2 TP3 = T_POINT_R_Dup1
U3 = AW1612_0
U4 U12 = RT9293B_0
U11 = RT9266PE_3

## Sheet 05 MISC.SchDoc
size 420 x 297 mm
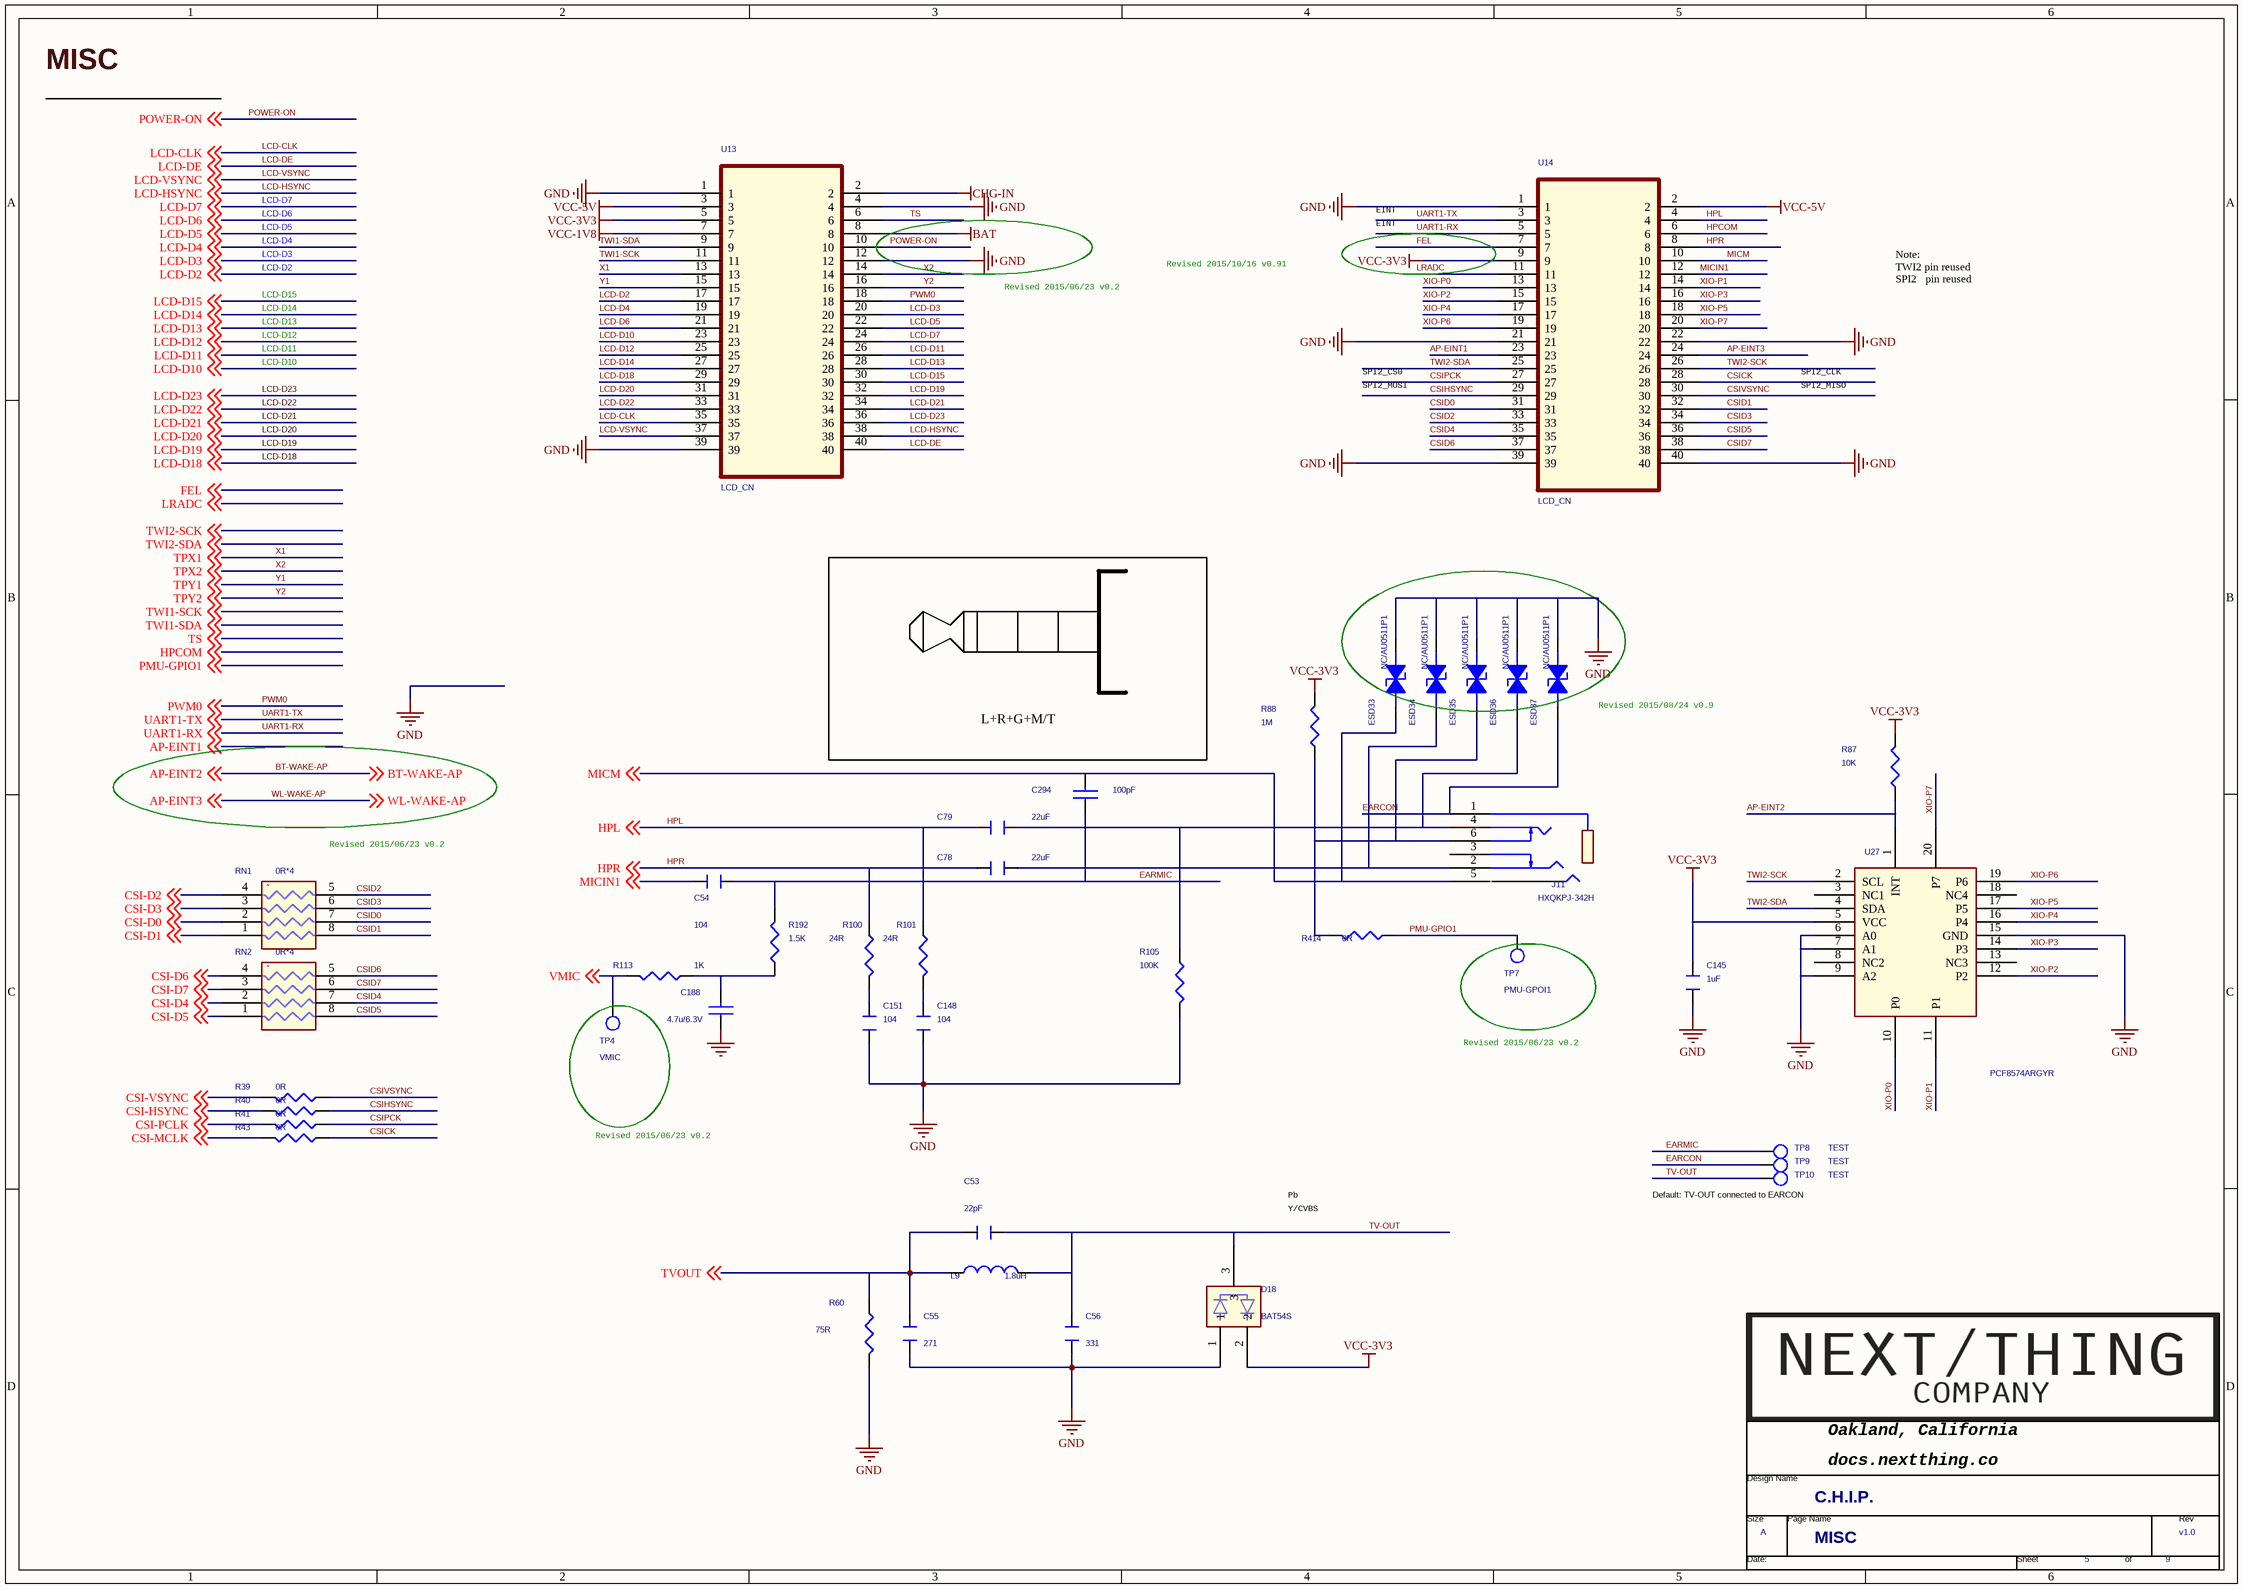
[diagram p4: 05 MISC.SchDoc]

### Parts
(Parts that share a designator on the sheet are numbered #1, #2 ... from top to bottom, then left to right.)
*#5  Page Count: 9  Page Number: 5  Page Size: A  Title: C.H.I.P.  RevCode: v1.0  Doc: MISC  (hidden comment: TitleBlock1-nextthing)  (graphical)
C53  22pF  [C0201]
C54  104  [C0201]
C55  271  [C0201]
C56  331  [C0201]
C78  22uF  [CC0805]
C79  22uF  [CC0805]
C145  1uF  [CC0402]
C148  104  [C0201]
C151  104  [C0201]
C188  4.7u/6.3V  [CC0603]
C294  100pF  [C0201]
D18  BAT54S  [SOT-23]
ESD33  NC/AU0511P1  [R0402]
ESD34  NC/AU0511P1  [R0402]
ESD35  NC/AU0511P1  [R0402]
ESD36  NC/AU0511P1  [R0402]
ESD37  NC/AU0511P1  [R0402]
J11  HXQKPJ-342H  [TSH-3865D]
L9  1.8uH  [L0603]
R39  0R  [R0603]
R40  0R  [R0603]
R41  0R  [R0603]
R43  0R  [R0603]
R60  75R  [C0201]
R87  10K  [C0201]
R88  1M  [C0201]
R100  24R  [R0402]
R101  24R  [R0402]
R105  100K  [R0402]
R113  1K  [C0201]
R192  1.5K  [C0201]
R414  0R  [0805]
RN1  0R*4  [RN0201]
RN2  0R*4  [RN0201]
TP4  VMIC  [TP40_SMD]
TP7  PMU-GPOI1  [TP40_SMD]
TP8  TEST  [TP30_SMD]
TP9  TEST  [TP30_SMD]
TP10  TEST  [TP30_SMD]
U13  LCD_CN  [CON2X20-PT2_54-5_2X31_2H2A]
U14  LCD_CN  [CON2X20-PT2_54-5_2X31_2H2A]
U27  PCF8574ARGYR  [SO16]

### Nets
BAT: U13.8
CHG-IN: U13.2
GND: C55.1 C56.1 C145.1 C148.2 C151.2 C188.1 D18.1 ESD33.1(ANODE) ESD34.1(ANODE) ESD35.1(ANODE) ESD36.1(ANODE) ESD37.1(ANODE) R60.2 R105.2 U13.1 U13.4 U13.12 U13.39 U14.1 U14.21 U14.22 U14.39 U14.40 U27.6(A0) U27.7(A1) U27.9(A2) U27.15(GND)  [project net AGND]
VCC-1V8: U13.7  [project net LDO5]
VCC-3V3: C145.2 D18.2 R87.2 R88.2 U13.5 U14.9 U27.5(VCC)  [project net HPVCC]
VCC-5V: U13.3 U14.2
AP-EINT1: U14.23 ; off-sheet AP-EINT1
AP-EINT2: R87.1 U27.1(INT) ; off-sheet AP-EINT2, off-sheet BT-WAKE-AP  [also labelled BT-WAKE-AP]
AP-EINT3: U14.24 ; off-sheet AP-EINT3, off-sheet WL-WAKE-AP  [also labelled WL-WAKE-AP]
CSI-D0: RN1.2(R2) ; off-sheet CSI-D0
CSI-D1: RN1.1(R1) ; off-sheet CSI-D1
CSI-D2: RN1.4(R4) ; off-sheet CSI-D2
CSI-D3: RN1.3(R3) ; off-sheet CSI-D3
CSI-D4: RN2.2(R2) ; off-sheet CSI-D4
CSI-D5: RN2.1(R1) ; off-sheet CSI-D5
CSI-D6: RN2.4(R4) ; off-sheet CSI-D6
CSI-D7: RN2.3(R3) ; off-sheet CSI-D7
CSI-HSYNC: R40.1 ; off-sheet CSI-HSYNC
CSI-MCLK: R43.2 ; off-sheet CSI-MCLK
CSI-PCLK: R41.1 ; off-sheet CSI-PCLK
CSI-VSYNC: R39.1 ; off-sheet CSI-VSYNC
CSICK: R43.1 U14.28
CSID0: RN1.7(R7) U14.31
CSID1: RN1.8(R8) U14.32
CSID2: RN1.5(R5) U14.33
CSID3: RN1.6(R6) U14.34
CSID4: RN2.7(R7) U14.35
CSID5: RN2.8(R8) U14.36
CSID6: RN2.5(R5) U14.37
CSID7: RN2.6(R6) U14.38
CSIHSYNC: R40.2 U14.29
CSIPCK: R41.2 U14.27
CSIVSYNC: R39.2 U14.30
EARCON: ESD37.2(CATHODE) J11.1 TP9.1(TP)
EARMIC: C54.2 C294.1 R192.2 TP8.1(TP)
FEL: U14.7 ; off-sheet FEL
HPCOM: U14.6 ; off-sheet HPCOM
HPL: C79.1 R101.1 U14.4 ; off-sheet HPL
HPR: C78.1 R100.1 U14.8 ; off-sheet HPR
LCD-CLK: U13.35 ; off-sheet LCD-CLK
LCD-D2: U13.17 ; off-sheet LCD-D2
LCD-D3: U13.20 ; off-sheet LCD-D3
LCD-D4: U13.19 ; off-sheet LCD-D4
LCD-D5: U13.22 ; off-sheet LCD-D5
LCD-D6: U13.21 ; off-sheet LCD-D6
LCD-D7: U13.24 ; off-sheet LCD-D7
LCD-D10: U13.23 ; off-sheet LCD-D10
LCD-D11: U13.26 ; off-sheet LCD-D11
LCD-D12: U13.25 ; off-sheet LCD-D12
LCD-D13: U13.28 ; off-sheet LCD-D13
LCD-D14: U13.27 ; off-sheet LCD-D14
LCD-D15: U13.30 ; off-sheet LCD-D15
LCD-D18: U13.29 ; off-sheet LCD-D18
LCD-D19: U13.32 ; off-sheet LCD-D19
LCD-D20: U13.31 ; off-sheet LCD-D20
LCD-D21: U13.34 ; off-sheet LCD-D21
LCD-D22: U13.33 ; off-sheet LCD-D22
LCD-D23: U13.36 ; off-sheet LCD-D23
LCD-DE: U13.40 ; off-sheet LCD-DE
LCD-HSYNC: U13.38 ; off-sheet LCD-HSYNC
LCD-VSYNC: U13.37 ; off-sheet LCD-VSYNC
LRADC: U14.11 ; off-sheet LRADC
MICIN1: C54.1 U14.12 ; off-sheet MICIN1
MICM: C294.2 ESD33.2(CATHODE) J11.5 U14.10 ; off-sheet MICM
PMU-GPIO1: R414.1 TP7.1(TP) ; off-sheet PMU-GPIO1
POWER-ON: U13.10 ; off-sheet POWER-ON
PWM0: U13.18 ; off-sheet PWM0  [project net PB2]
TPX1: U13.13 ; off-sheet TPX1  [also labelled X1]
TPX2: U13.14 ; off-sheet TPX2  [also labelled X2]
TPY1: U13.15 ; off-sheet TPY1  [also labelled Y1]
TPY2: U13.16 ; off-sheet TPY2  [also labelled Y2]
TS: U13.6 ; off-sheet TS
TV-OUT: C53.2 C56.2 D18.3 L9.2 TP10.1(TP)
TVOUT: C53.1 C55.2 L9.1 R60.1 ; off-sheet TVOUT
TWI1-SCK: U13.11 ; off-sheet TWI1-SCK  [project net PB15]
TWI1-SDA: U13.9 ; off-sheet TWI1-SDA  [project net PB16]
TWI2-SCK: U14.26 U27.2(SCL) ; off-sheet TWI2-SCK  [project net PB17]
TWI2-SDA: U14.25 U27.4(SDA) ; off-sheet TWI2-SDA  [project net PB18]
UART1-RX: U14.5 ; off-sheet UART1-RX
UART1-TX: U14.3 ; off-sheet UART1-TX  [project net PG3]
VMIC: R113.2 TP4.1(TP) ; off-sheet VMIC
XIO-P0: U14.13 U27.10(P0)
XIO-P1: U14.14 U27.11(P1)
XIO-P2: U14.15 U27.12(P2)
XIO-P3: U14.16 U27.14(P3)
XIO-P4: U14.17 U27.16(P4)
XIO-P5: U14.18 U27.17(P5)
XIO-P6: U14.19 U27.19(P6)
XIO-P7: U14.20 U27.20(P7)
NetC78_2: C78.2 ESD34.2(CATHODE) J11.2
NetC79_2: C79.2 ESD36.2(CATHODE) J11.4 R105.1
NetC148_1: C148.1 R101.2
NetC151_1: C151.1 R100.2
NetC188_2: C188.2 R113.1 R192.1
NetESD35_2: ESD35.2(CATHODE) J11.6 R88.1 R414.2

Not connected (* = marked no-connect by the designer): J11 3; U27 3(NC1) 8(NC2) 13(NC3) 18(NC4)

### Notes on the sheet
- MISC
- EINT
- Note:
  TWI2 pin reused
  SPI2   pin reused
- Revised 2015/06/23 v0.2
- Revised 2015/10/16 v0.91
- SPI2_MOSI
- SPI2_CS0
- SPI2_MISO
- SPI2_CLK
- L+R+G+M/T
- (near ESD37) Revised 2015/08/24 v0.9
- (near RN1) Revised 2015/06/23 v0.2
- Pb
- (near TP10) Default: TV-OUT connected to EARCON
- Y/CVBS

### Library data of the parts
C53-C56 C145 = CAPACITOR
C78 C79 = CAPACITOR_0: PAGE: 1
C148 C151 = CAPACITOR_0_Dup1: PAGE: 1
C188 = CAP NP: 0603 2.2uF X5R 6.3V +/-10%/0603 2.2uF X5R 6.3V +/-10%/0603 2.2uF X5R 6.3V +/-20%; Part Number: C0603B225K006AT/GRM185R60J225KE26/C0603B225M006AT; Singconn Part Number: EJ225K6V3631; SPREADWIN PN: C0200004A/C0200004C/C0200004D; Vendor: YIXING/MURATA/YIXING
C294 = CAP NP: 0402 100pF C0G 50V +/-5%; PART_NUMBER: GRM1555C1H180JZ01; Part Number: GRM1555C1H101JZ01/C0402CG101J050AT; Vendor: MURATA/YIXING; SPREADWIN PN: C0100019A/C0100019D
D18 = DIODE_DUAL
ESD33-ESD37 = 1_1.5KE100A: as ESD38 on sheet 04 POWER
J11 = PHONOJACK_1
L9 = INDUCTOR_1
R39-R41 R43 = RESISTOR_0
R60 = RESISTOR: ROOM: TVLCD
R87 R88 R113 R192 = RESISTOR_Dup1
R100 R101 R105 = ?_0_Dup1
R414 = R1 0805
RN1 RN2 = R-PACK4_1
TP4 TP7-TP10 = T_POINT_R_Dup1
U13 U14 = CNLCD_0
U27 = PCF8574T_1

## Sheet 06 SDIO WIFI&BT.SchDoc
size 420 x 297 mm
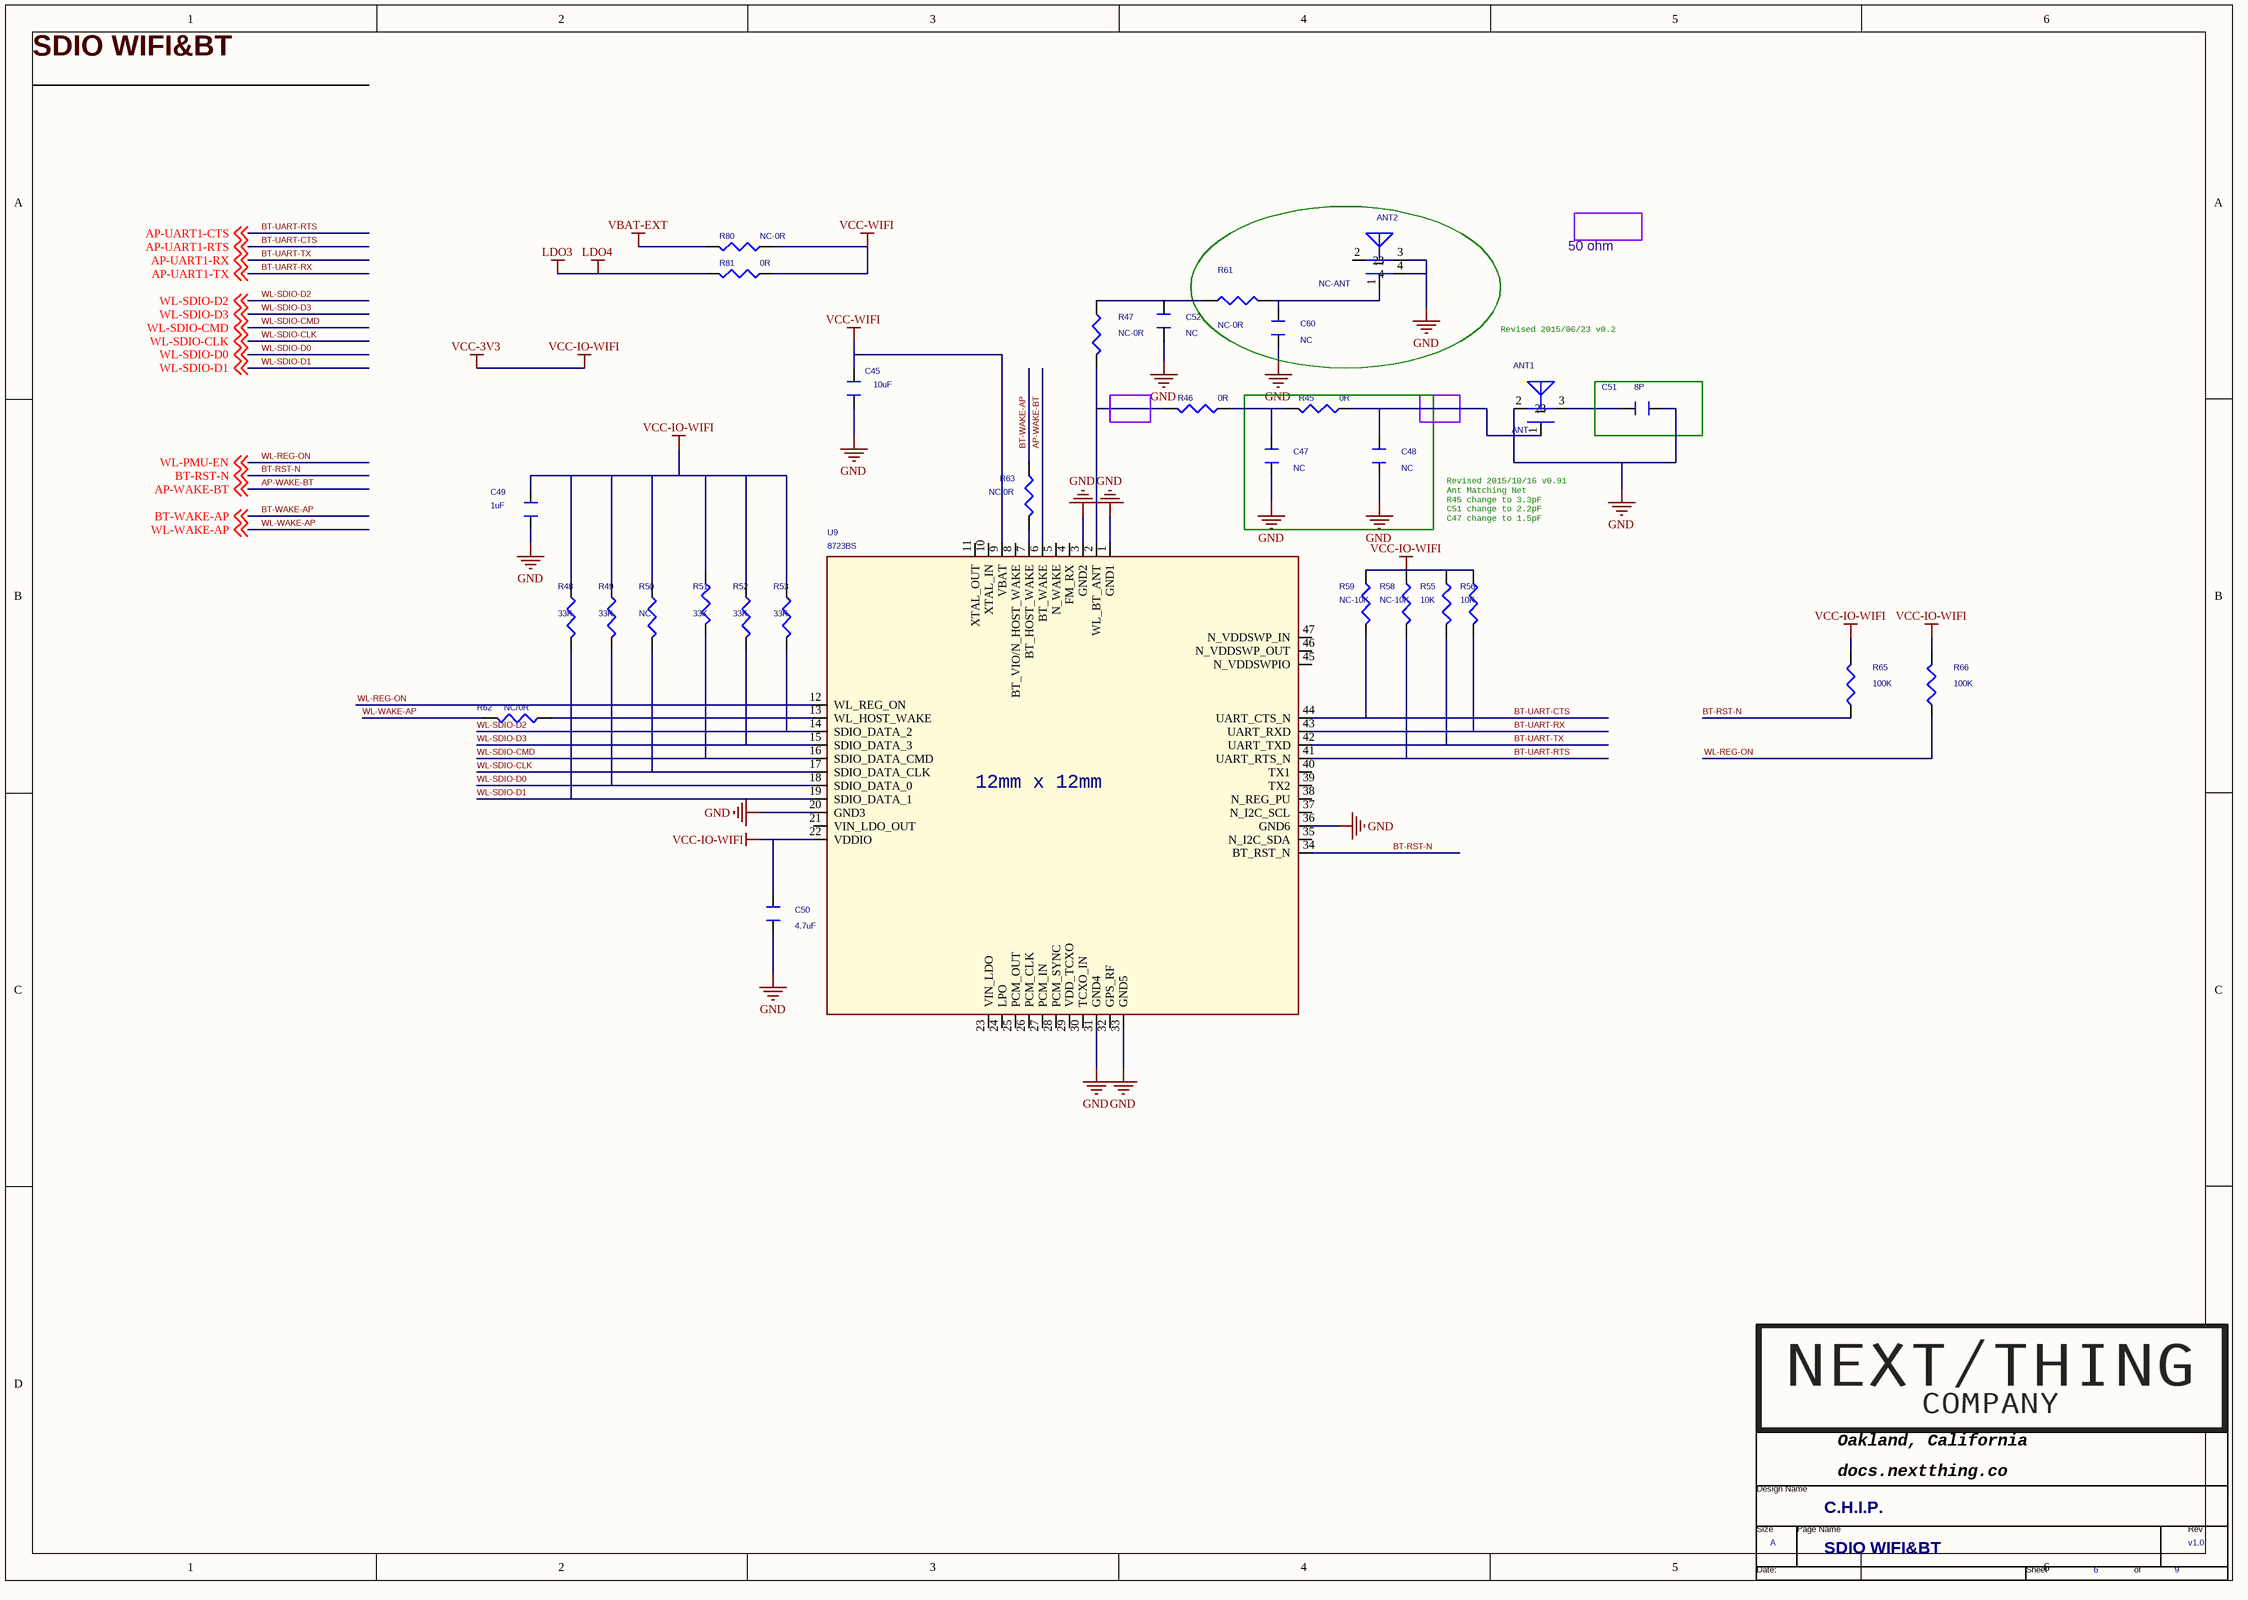
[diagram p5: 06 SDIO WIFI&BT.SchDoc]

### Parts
(Parts that share a designator on the sheet are numbered #1, #2 ... from top to bottom, then left to right.)
*#6  Page Count: 9  Page Number: 6  Page Size: A  Title: C.H.I.P.  RevCode: v1.0  Doc: SDIO WIFI&BT  (hidden comment: TitleBlock1-nextthing)  (graphical)
ANT1  ANT  [WIFI-1206]
ANT2  NC-ANT  [WIFI-ANT-SD73412-011H1_3A]
C45  10uF  [CC0603]
C47  NC  [C0201]
C48  NC  [C0201]
C49  1uF  [CC0402]
C50  4.7uF  [CC0603]
C51  8P  [C0201]
C52  NC  [C0201]
C60  NC  [C0201]
R45  0R  [C0201]
R46  0R  [C0201]
R47  NC-0R  [C0201]
R48  33K  [C0201]
R49  33K  [C0201]
R50  NC  [C0201]
R51  33K  [C0201]
R52  33K  [C0201]
R53  33K  [C0201]
R55  10K  [C0201]
R56  10K  [C0201]
R58  NC-10K  [C0201]
R59  NC-10K  [C0201]
R61  NC-0R  [C0201]
R62  NC/0R  [C0201]
R63  NC/0R  [C0201]
R65  100K  [C0201]
R66  100K  [C0201]
R80  NC-0R  [R0805]
R81  0R  [R0805]
U9  8723BS  [QFN44-AP6476-12X12H1_6A]

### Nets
GND: ANT1.2 ANT2.3 ANT2.4 C45.1 C47.2 C48.2 C49.1 C50.2 C51.2 C52.2 C60.2 U9.1(GND1) U9.3(GND2) U9.20(GND3) U9.31(GND4) U9.33(GND5) U9.36(GND6)  [project net AGND]
LDO3: R81.2  [also labelled LDO4]
VBAT-EXT: R80.2
VCC-3V3: C49.2 C50.1 R48.1 R49.1 R50.1 R51.1 R52.1 R53.1 R55.1 R56.1 R58.1 R59.1 R65.2 R66.2 U9.22(VDDIO)  [also labelled VCC-IO-WIFI]  [project net HPVCC]
VCC-WIFI: C45.2 R80.1 R81.1 U9.9(VBAT)
AP-WAKE-BT: U9.6(BT_WAKE) ; off-sheet AP-WAKE-BT
BT-RST-N: R65.1 U9.34(BT_RST_N) ; off-sheet BT-RST-N
BT-UART-CTS: R59.2 U9.44(UART_CTS_N) ; off-sheet AP-UART1-RTS  [also labelled AP-UART1-RTS]
BT-UART-RTS: R58.2 U9.41(UART_RTS_N) ; off-sheet AP-UART1-CTS  [also labelled AP-UART1-CTS]
BT-UART-RX: R56.2 U9.43(UART_RXD) ; off-sheet AP-UART1-TX  [also labelled AP-UART1-TX]
BT-UART-TX: R55.2 U9.42(UART_TXD) ; off-sheet AP-UART1-RX  [also labelled AP-UART1-RX]
BT-WAKE-AP: R63.2 ; off-sheet BT-WAKE-AP  [project net AP-EINT2]
WL-PMU-EN: R66.1 U9.12(WL_REG_ON) ; off-sheet WL-PMU-EN  [also labelled WL-REG-ON]  [project net PC19]
WL-SDIO-CLK: R50.2 U9.17(SDIO_DATA_CLK) ; off-sheet WL-SDIO-CLK  [project net PF2]
WL-SDIO-CMD: R51.2 U9.16(SDIO_DATA_CMD) ; off-sheet WL-SDIO-CMD  [project net PF3]
WL-SDIO-D0: R49.2 U9.18(SDIO_DATA_0) ; off-sheet WL-SDIO-D0  [project net PF1]
WL-SDIO-D1: R48.2 U9.19(SDIO_DATA_1) ; off-sheet WL-SDIO-D1  [project net PF0]
WL-SDIO-D2: R53.2 U9.14(SDIO_DATA_2) ; off-sheet WL-SDIO-D2  [project net PF5]
WL-SDIO-D3: R52.2 U9.15(SDIO_DATA_3) ; off-sheet WL-SDIO-D3  [project net PF4]
WL-WAKE-AP: R62.2 ; off-sheet WL-WAKE-AP  [project net AP-EINT3]
NetANT1_1: ANT1.1 C48.1 R45.1
NetANT1_3: ANT1.3 C51.1
NetANT2_1: ANT2.1 C60.1 R61.2
NetC47_1: C47.1 R45.2 R46.1
NetC52_1: C52.1 R47.1 R61.1
NetR46_2: R46.2 R47.2 U9.2(WL_BT_ANT)
NetR62_1: R62.1 U9.13(WL_HOST_WAKE)
NetR63_1: R63.1 U9.7(BT_HOST_WAKE)

Not connected (* = marked no-connect by the designer): ANT2 2; U9 4(FM_RX) 5(N_WAKE) 8(BT_VIO/N_HOST_WAKE) 10(XTAL_IN) 11(XTAL_OUT) 21(VIN_LDO_OUT) 23(VIN_LDO) 24(LPO) 25(PCM_OUT) 26(PCM_CLK) 27(PCM_IN) 28(PCM_SYNC) 29(VDD_TCXO) 30(TCXO_IN) 32(GPS_RF) 35(N_I2C_SDA) 37(N_I2C_SCL) 38(N_REG_PU) 39(TX2) 40(TX1) 45(N_VDDSWPIO) 46(N_VDDSWP_OUT) 47(N_VDDSWP_IN)

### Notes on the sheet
- SDIO WIFI&BT
- 50 ohm
- Revised 2015/06/23 v0.2
- Revised 2015/10/16 v0.91
  Ant Matching Net
  R45 change to 3.3pF
  C51 change to 2.2pF
  C47 change to 1.5pF

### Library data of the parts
ANT1 = ANT_2
ANT2 = ANT_4
C45 C47-C52 C60 = CAPACITOR_0_Dup4: PAGE: 2
R45-R53 R55 R56 R58 R59 R61-R63 R65 R66 R80 R81 = R_Dup1
U9 = AP6493_4: Device: AMPAK_SIP; QVL: AMPAK; ORCAD_LIB: MODULE

## Sheet 07 USB.SchDoc
size 420 x 297 mm
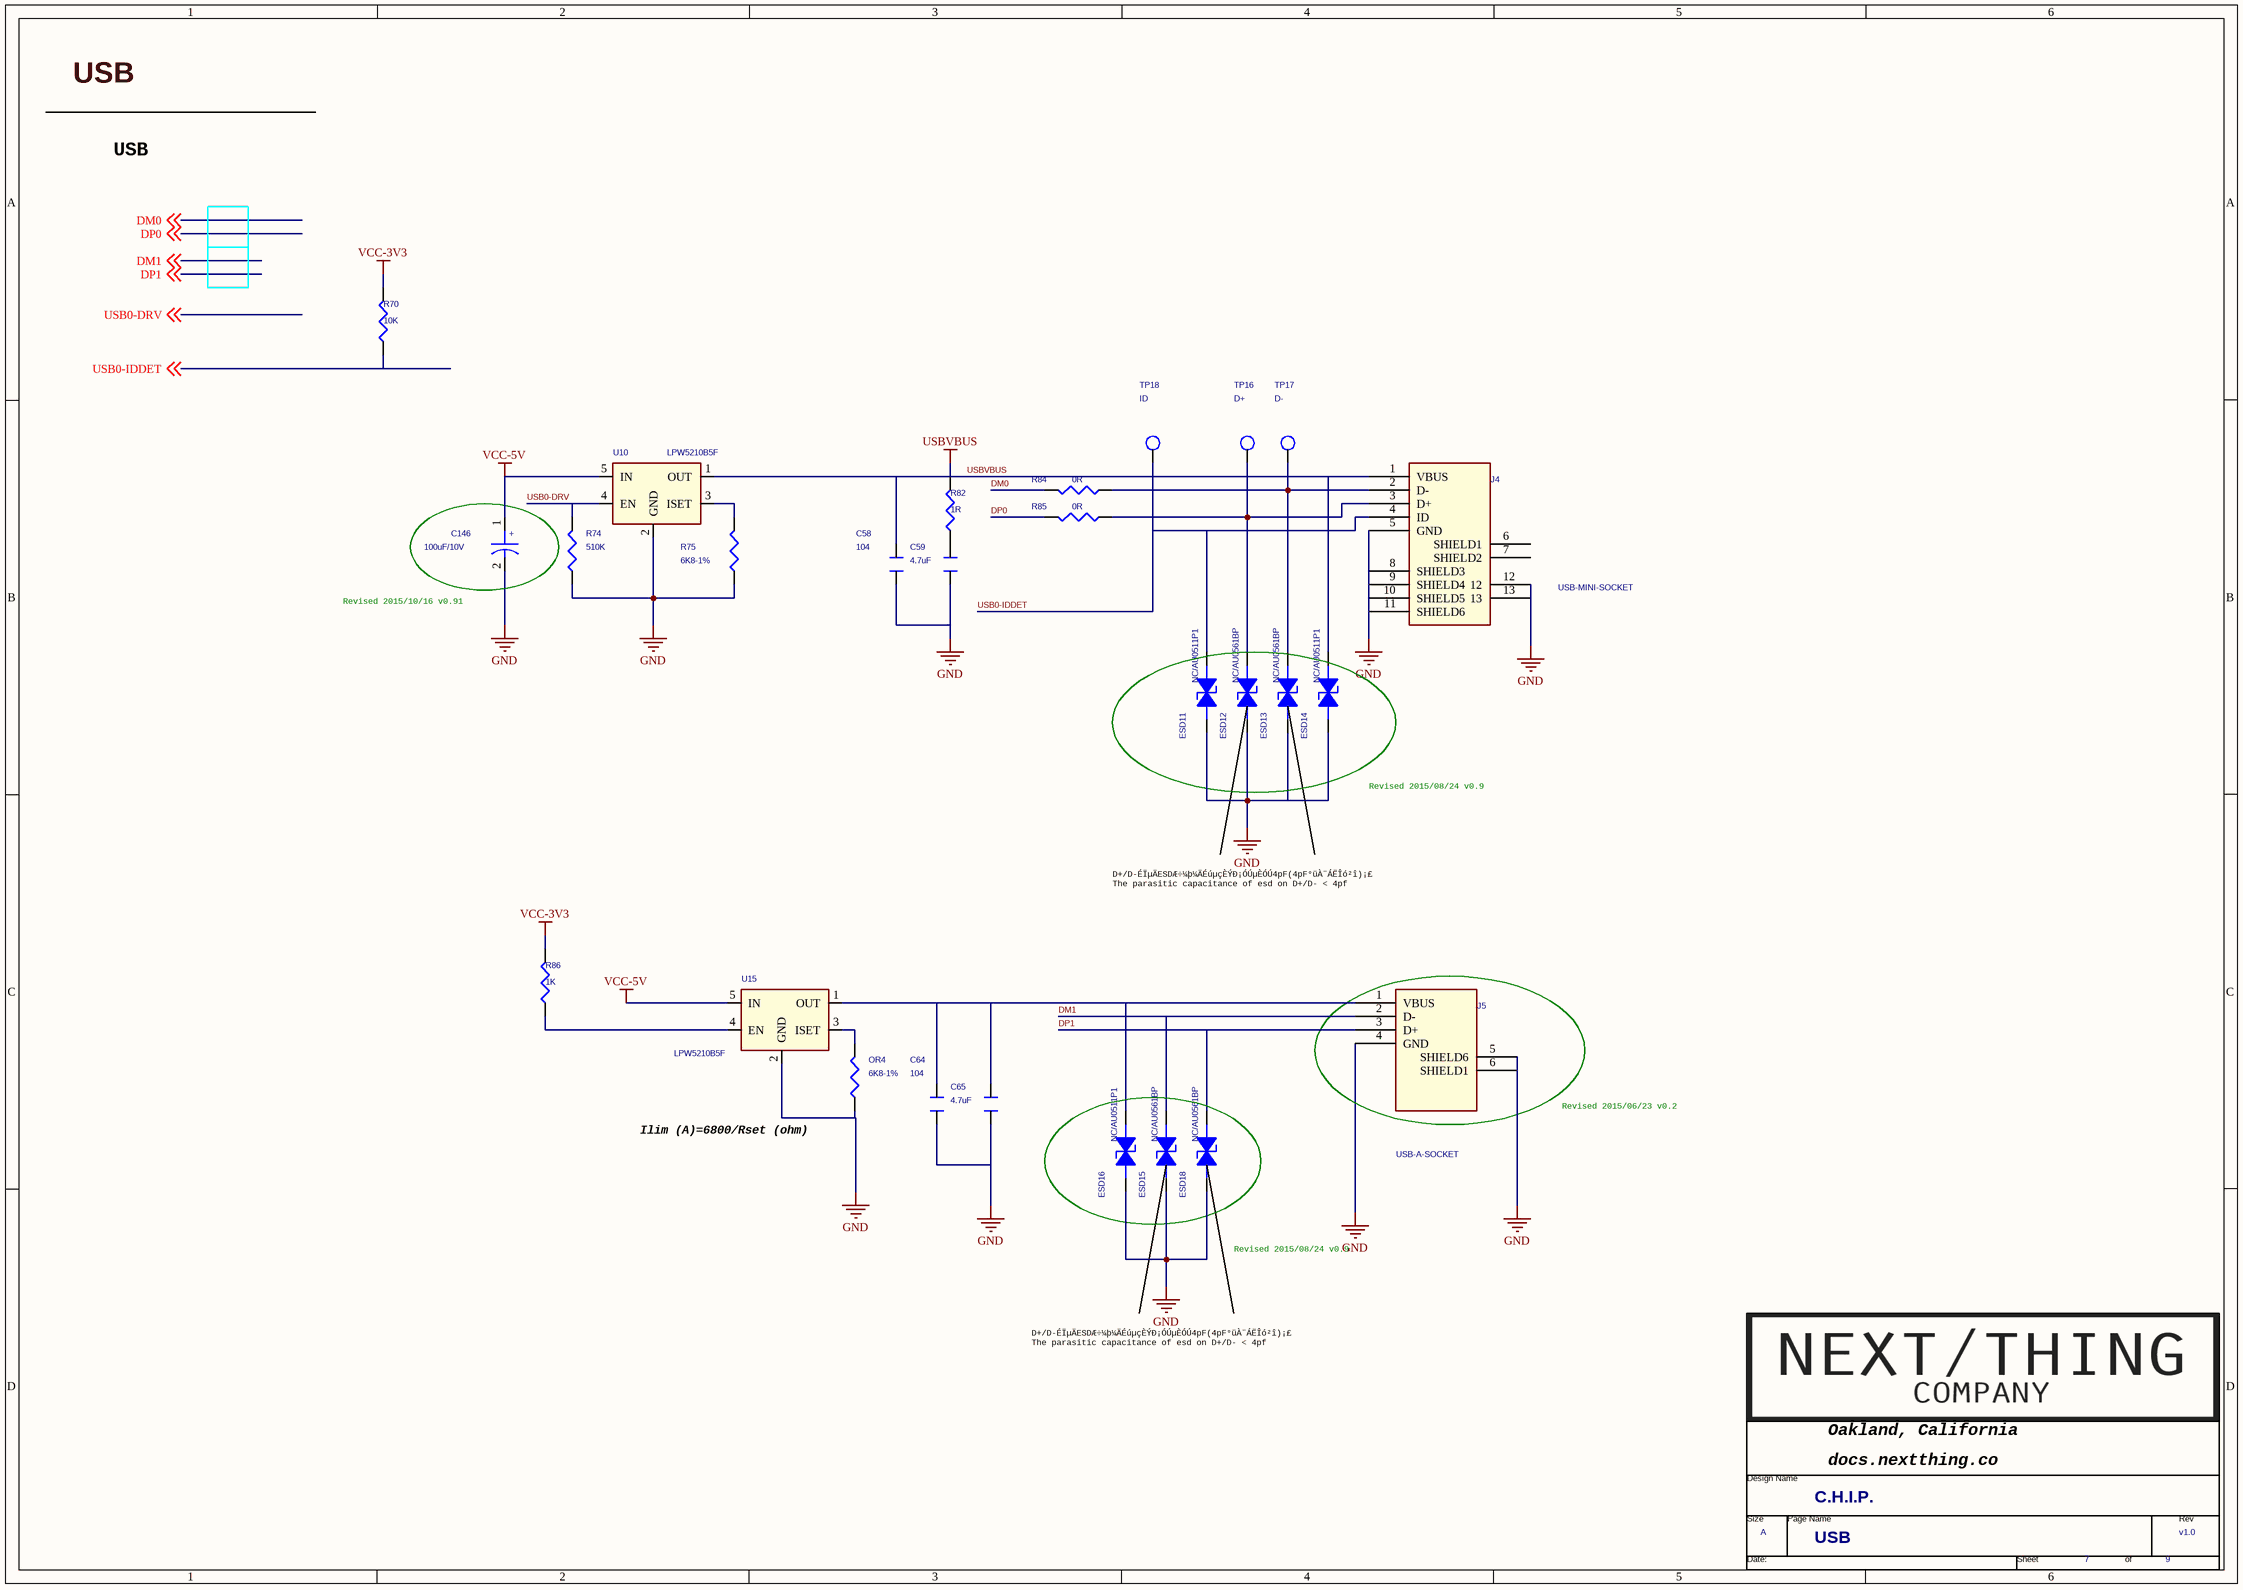
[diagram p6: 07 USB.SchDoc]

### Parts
(Parts that share a designator on the sheet are numbered #1, #2 ... from top to bottom, then left to right.)
*#7  Page Count: 9  Page Number: 7  Page Size: A  Title: C.H.I.P.  RevCode: v1.0  Doc: USB  (hidden comment: TitleBlock1-nextthing)  (graphical)
C58  104  [C0201]
C59  4.7uF  [CC0603]
C64  104  [C0201]
C65  4.7uF  [CC0603]
C146  100uF/10V  [CT1210]
ESD11  NC/AU0511P1  [R0402]
ESD12  NC/AU0561BP  [R0402]
ESD13  NC/AU0561BP  [R0402]
ESD14  NC/AU0511P1  [R0402]
ESD15  NC/AU0561BP  [R0402]
ESD16  NC/AU0511P1  [R0402]
ESD18  NC/AU0561BP  [R0402]
J4  USB-MINI-SOCKET  [USB_MINI_AB]
J5  USB-A-SOCKET  [USB_MINI_AB]
OR4  6K8-1%  [C0201]
R70  10K  [C0201]
R74  510K  [C0201]
R75  6K8-1%  [C0201]
R82  1R  [R0402]
R84  0R  [C0201]
R85  0R  [C0201]
R86  1K  [C0201]
TP16  D+  [tp40_smd]
TP17  D-  [tp40_smd]
TP18  ID  [tp40_smd]
U10  LPW5210B5F  [SOT23-6]
U15  LPW5210B5F  [SOT23-6]

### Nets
GND: C58.1 C59.1 C64.1 C65.1 C146.2 ESD11.2(CATHODE) ESD12.2(CATHODE) ESD13.2(CATHODE) ESD14.2(CATHODE) ESD15.2(CATHODE) ESD16.2(CATHODE) ESD18.2(CATHODE) J4.5(GND) J4.8(SHIELD3) J4.9(SHIELD4) J4.10(SHIELD5) J4.11(SHIELD6) J4.12 J4.13 J5.4(GND) J5.5(SHIELD6) J5.6(SHIELD1) OR4.1 R74.1 R75.1 U10.2(GND) U15.2(GND)  [project net AGND]
USBVBUS: C58.2 ESD14.1(ANODE) J4.1(VBUS) R82.2 U10.1(OUT)
VCC-3V3: R70.2 R86.2  [project net HPVCC]
VCC-5V: C146.1 U10.5(IN) U15.5(IN)
DM0: R84.2 ; off-sheet DM0
DM1: ESD15.1(ANODE) J5.2(D-) ; off-sheet DM1
DP0: R85.2 ; off-sheet DP0
DP1: ESD18.1(ANODE) J5.3(D+) ; off-sheet DP1
USB0-DRV: R74.2 U10.4(EN) ; off-sheet USB0-DRV  [project net PB10]
USB0-IDDET: ESD11.1(ANODE) J4.4(ID) R70.1 TP18.1(TP) ; off-sheet USB0-IDDET  [project net PG2]
NetC59_2: C59.2 R82.1
NetC64_2: C64.2 C65.2 ESD16.1(ANODE) J5.1(VBUS) U15.1(OUT)
NetESD12_1: ESD12.1(ANODE) J4.3(D+) R85.1 TP16.1(TP)
NetESD13_1: ESD13.1(ANODE) J4.2(D-) R84.1 TP17.1(TP)
NetOR4_2: OR4.2 U15.3(ISET)
NetR75_2: R75.2 U10.3(ISET)
NetR86_1: R86.1 U15.4(EN)

Not connected (* = marked no-connect by the designer): J4 6(SHIELD1) 7(SHIELD2)

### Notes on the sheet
- USB
- Revised 2015/10/16 v0.91
- Revised 2015/08/24 v0.9
- D+/D-ÉÏµÄESDÆ÷¼þ¼ÄÉúµçÈÝÐ¡ÓÚµÈÓÚ4pF(4pF°üÀ¨ÁËÎó²î)¡£
  The parasitic capacitance of esd on D+/D- < 4pf
- Ilim (A)=6800/Rset (ohm)
- Revised 2015/06/23 v0.2

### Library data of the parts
C58 C59 C64 C65 = CAPACITOR
C146 = CAPACITOR_POL: ROOM: MODEM
ESD11-ESD16 ESD18 = 1_1.5KE100A: as ESD38 on sheet 04 POWER
J4 = USB_MINI_SOCKET_2
J5 = USB_MINI_SOCKET_5
OR4 R70 R74 R75 R82 R86 = R_Dup2
R84 R85 = RESISTOR_Dup1
TP16-TP18 = T_POINT_R
U10 U15 = RT9266PE_2

## Sheet 08 BESIDE CPU.SchDoc
size 420 x 297 mm
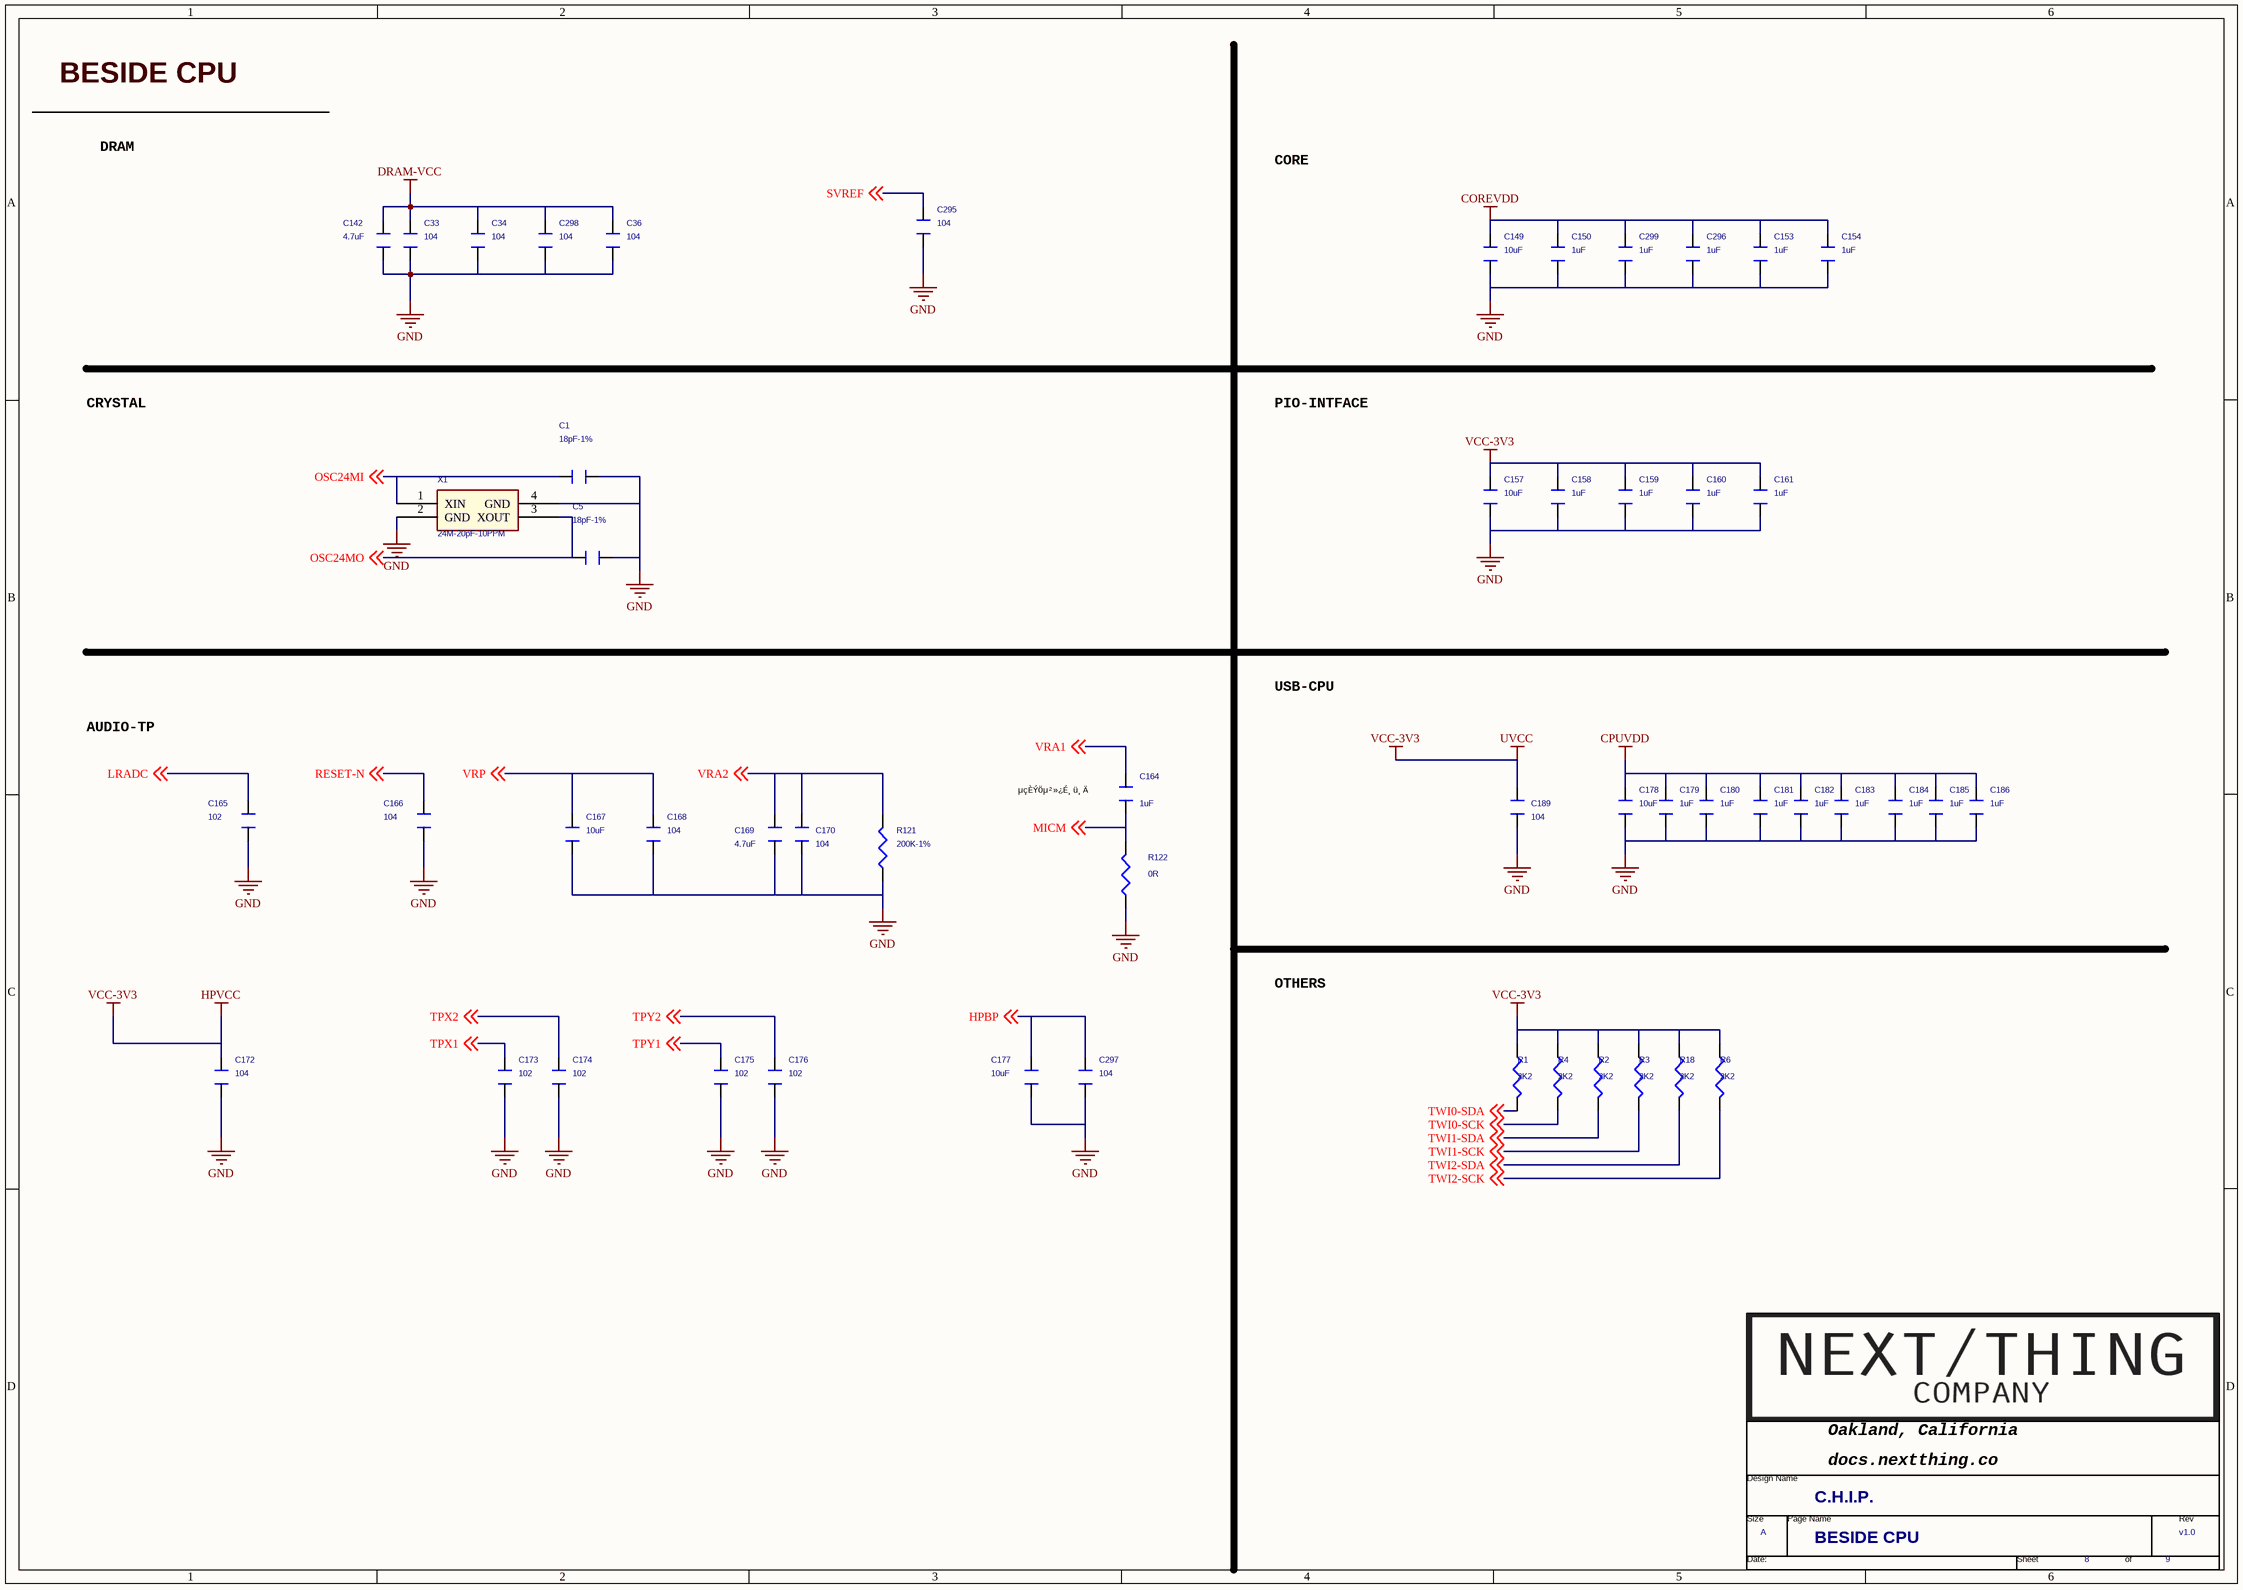
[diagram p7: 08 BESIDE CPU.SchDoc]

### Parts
(Parts that share a designator on the sheet are numbered #1, #2 ... from top to bottom, then left to right.)
*#8  Page Count: 9  Page Number: 8  Page Size: A  Title: C.H.I.P.  RevCode: v1.0  Doc: BESIDE CPU  (hidden comment: TitleBlock1-nextthing)  (graphical)
C1  18pF-1%  [C0201]
C5  18pF-1%  [C0201]
C33  104  [C0201]
C34  104  [C0201]
C36  104  [C0201]
C142  4.7uF  [C0402]
C149  10uF  [C0603]
C150  1uF  [C0402]
C153  1uF  [C0402]
C154  1uF  [C0402]
C157  10uF  [C0603]
C158  1uF  [C0402]
C159  1uF  [C0402]
C160  1uF  [C0402]
C161  1uF  [C0402]
C164  1uF  [C0402]
C165  102  [C0201]
C166  104  [C0201]
C167  10uF  [C0603]
C168  104  [C0201]
C169  4.7uF  [C0402]
C170  104  [C0201]
C172  104  [C0201]
C173  102  [C0201]
C174  102  [C0201]
C175  102  [C0201]
C176  102  [C0201]
C177  10uF  [C0603]
C178  10uF  [C0603]
C179  1uF  [C0402]
C180  1uF  [C0402]
C181  1uF  [C0402]
C182  1uF  [C0402]
C183  1uF  [C0402]
C184  1uF  [C0402]
C185  1uF  [C0402]
C186  1uF  [C0402]
C189  104  [C0201]
C295  104  [C0201]
C296  1uF  [C0402]
C297  104  [C0201]
C298  104  [C0201]
C299  1uF  [C0402]
R1  2K2  [C0201]
R2  2K2  [C0201]
R3  2K2  [C0201]
R4  2K2  [C0201]
R6  2K2  [C0201]
R18  2K2  [C0201]
R121  200K-1%  [C0201]
R122  0R  [C0201]
X1  24M-20pF-10PPM  [CRY-3225]

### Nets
COREVDD: C149.1 C150.1 C153.1 C154.1 C296.1 C299.1  [project net CORE-VDD]
CPUVDD: C178.1 C179.1 C180.1 C181.1 C182.1 C183.1 C184.1 C185.1 C186.1  [project net CPU-1V2]
DRAM-VCC: C33.2 C34.2 C36.2 C142.2 C298.2
GND: C1.1 C5.1 C33.1 C34.1 C36.1 C142.1 C149.2 C150.2 C153.2 C154.2 C157.2 C158.1 C159.1 C160.1 C161.1 C165.1 C166.1 C167.1 C168.1 C169.1 C170.1 C172.1 C173.1 C174.1 C175.1 C176.1 C177.1 C178.2 C179.2 C180.2 C181.2 C182.2 C183.2 C184.2 C185.2 C186.2 C189.1 C295.1 C296.2 C297.1 C298.1 C299.2 R121.1 R122.1 X1.2(GND) X1.4(GND)  [project net AGND]
HPVCC: C157.1 C158.2 C159.2 C160.2 C161.2 C172.2 C189.2 R1.1 R2.1 R3.1 R4.1 R6.1 R18.1  [also labelled UVCC, VCC-3V3]
HPBP: C177.2 C297.2 ; off-sheet HPBP
LRADC: C165.2 ; off-sheet LRADC
MICM: C164.1 R122.2 ; off-sheet MICM
OSC24MI: C1.2 X1.1(XIN) ; off-sheet OSC24MI
OSC24MO: C5.2 X1.3(XOUT) ; off-sheet OSC24MO
RESET-N: C166.2 ; off-sheet RESET-N  [project net RESET]
SVREF: C295.2 ; off-sheet SVREF
TPX1: C173.2 ; off-sheet TPX1
TPX2: C174.2 ; off-sheet TPX2
TPY1: C175.2 ; off-sheet TPY1
TPY2: C176.2 ; off-sheet TPY2
TWI0-SCK: R4.2 ; off-sheet TWI0-SCK  [project net PB0]
TWI0-SDA: R1.2 ; off-sheet TWI0-SDA  [project net PB1]
TWI1-SCK: R3.2 ; off-sheet TWI1-SCK  [project net PB15]
TWI1-SDA: R2.2 ; off-sheet TWI1-SDA  [project net PB16]
TWI2-SCK: R6.2 ; off-sheet TWI2-SCK  [project net PB17]
TWI2-SDA: R18.2 ; off-sheet TWI2-SDA  [project net PB18]
VRA1: C164.2 ; off-sheet VRA1
VRA2: C169.2 C170.2 R121.2 ; off-sheet VRA2
VRP: C167.2 C168.2 ; off-sheet VRP

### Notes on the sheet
- BESIDE CPU
- DRAM
- CORE
- CRYSTAL
- PIO-INTFACE
- AUDIO-TP
- USB-CPU
- µçÈÝÖµ²»¿É¸ü¸Ä
- OTHERS

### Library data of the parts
C1 C5 C33 C34 C36 C142 C158-C161 C167 C173-C177 C295 C297 C298 = CAPACITOR_0_Dup4: PAGE: 2
C149 C150 C153 C154 C157 C178-C186 C296 C299 = CAPACITOR_0_Dup3: PAGE: 1
C164-C166 C168-C170 = CAPACITOR_0_Dup4
C172 C189 = CAPACITOR_0_Dup4: PAGE: 3
R1-R4 R6 R18 R121 R122 = R_Dup2
X1 = CRYSTAL-4_3: Crystal 24MHz 20pF 10ppm  -30 to +85; PART NUMBER: 7M24000004; Vendor: TXC; SPREADWIN PN: U3000019A

## Sheet 09 DDR3.SchDoc
size 420 x 297 mm
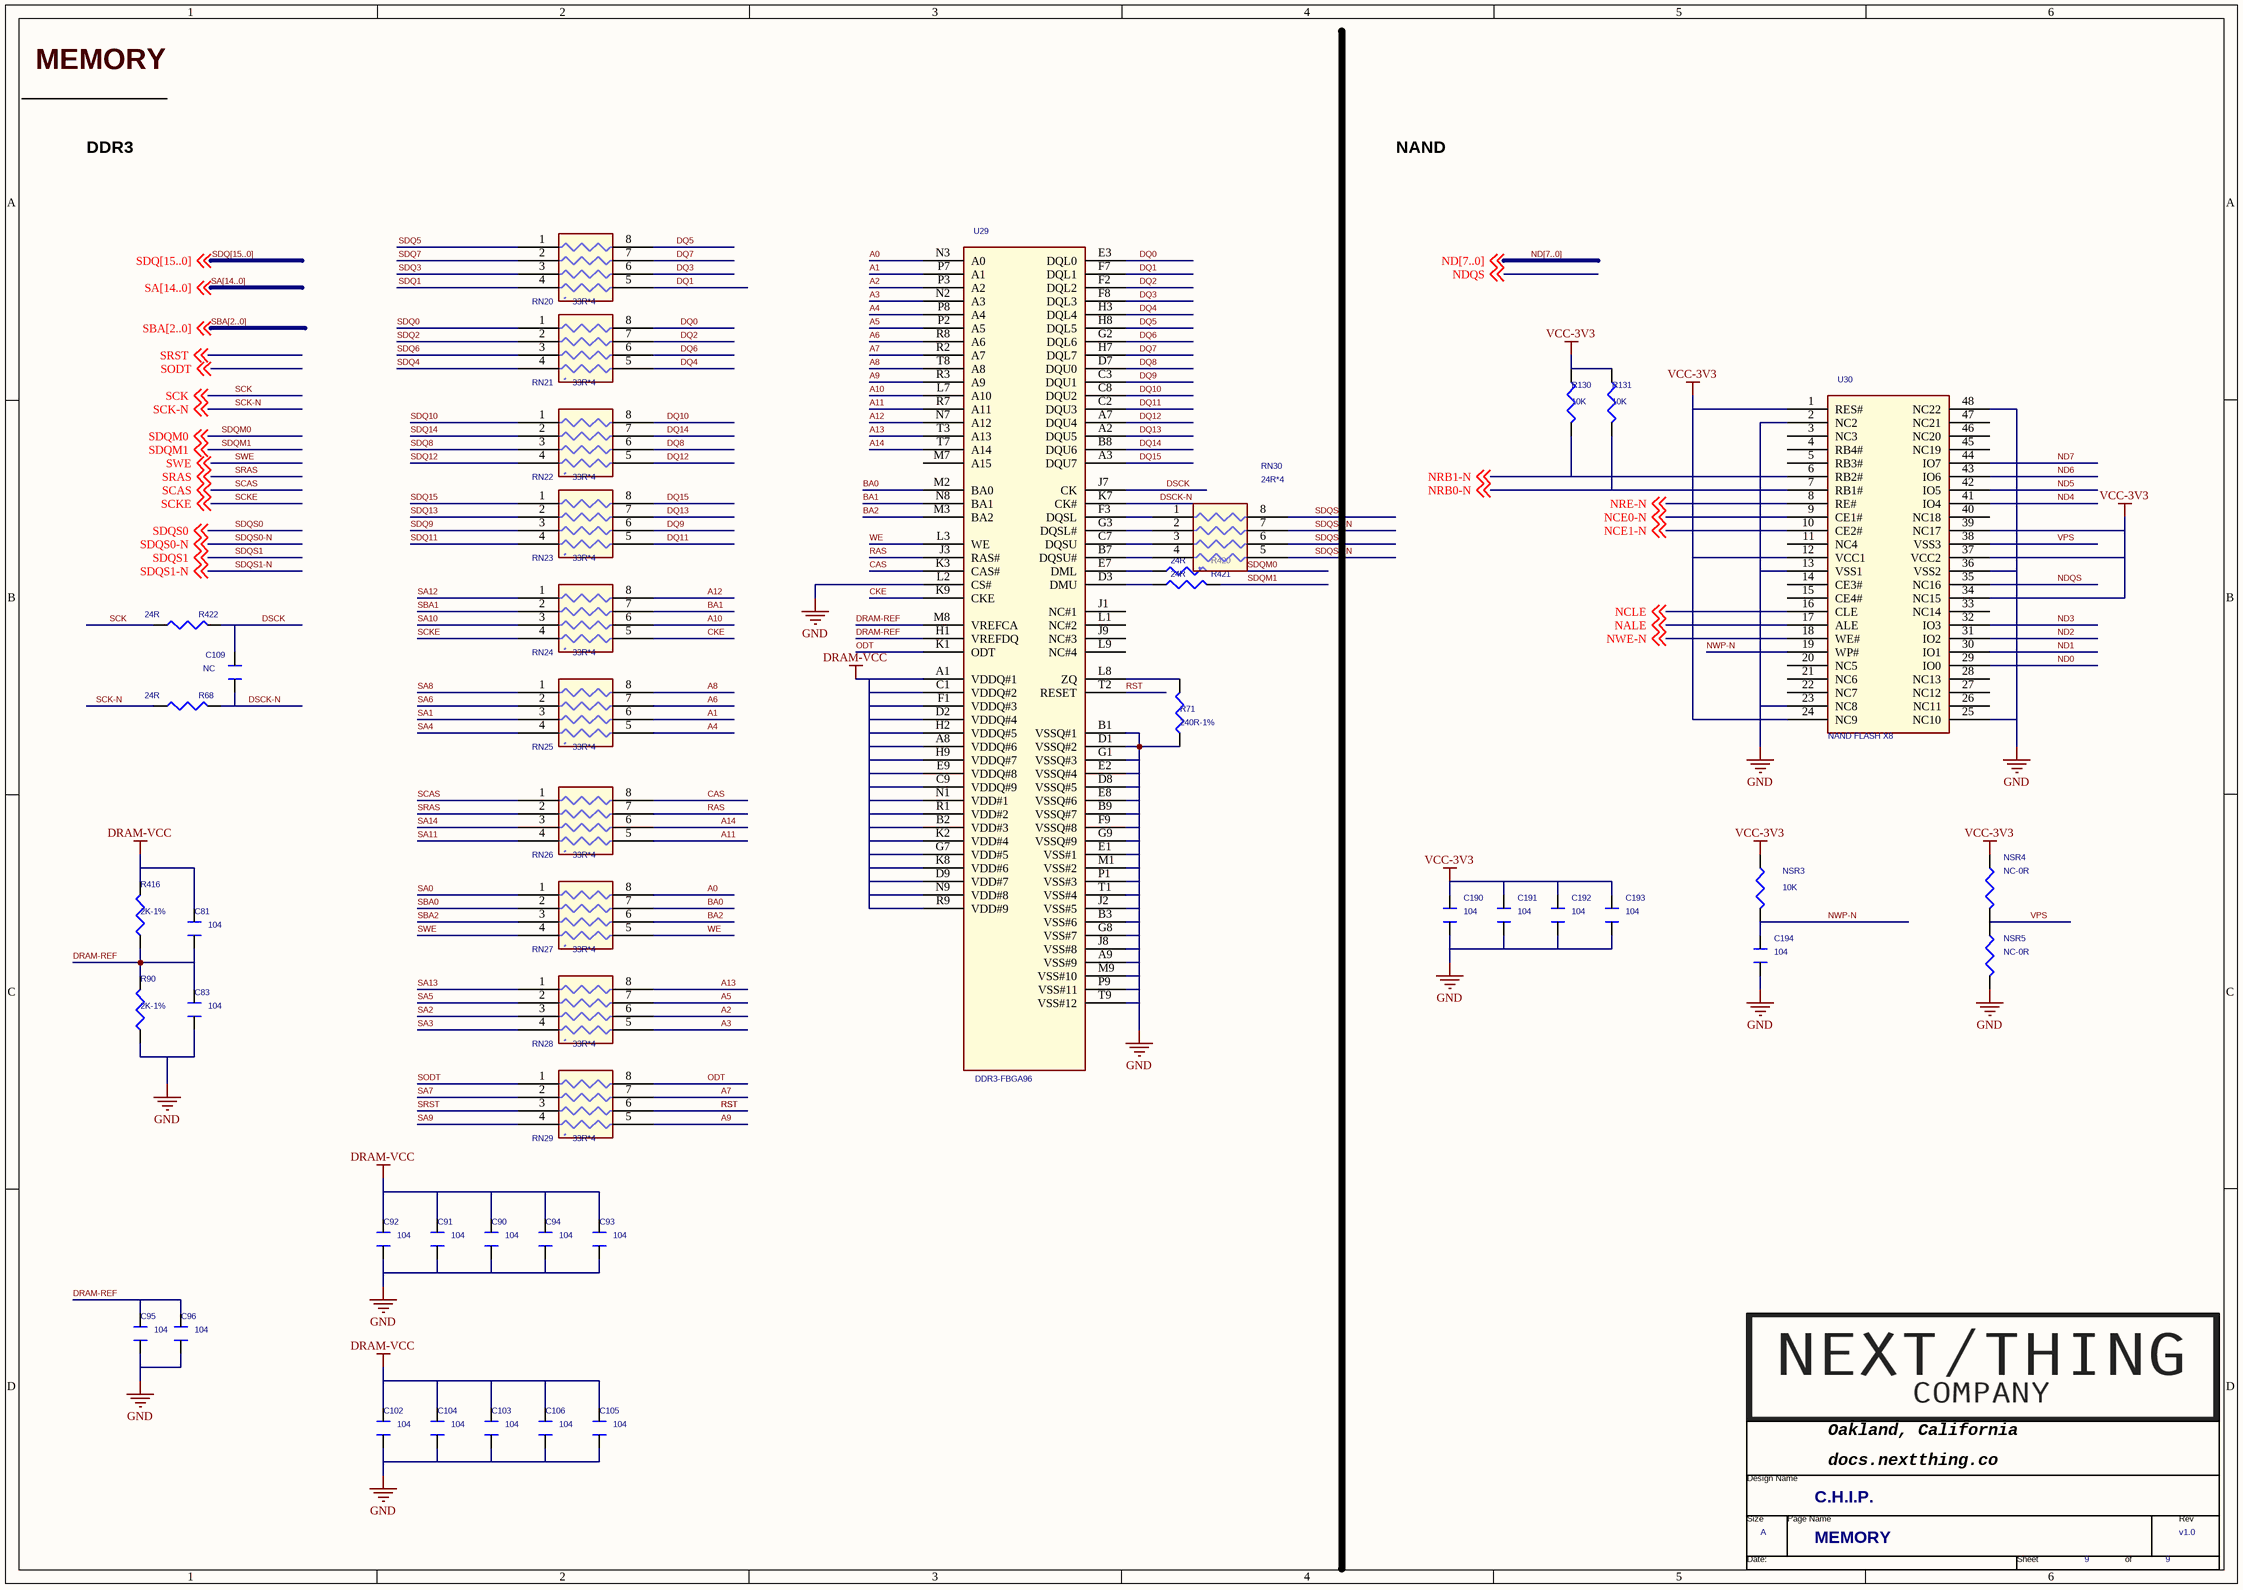
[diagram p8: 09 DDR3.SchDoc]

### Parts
(Parts that share a designator on the sheet are numbered #1, #2 ... from top to bottom, then left to right.)
*#9  Page Count: 9  Page Size: A  Title: C.H.I.P.  RevCode: v1.0  Doc: MEMORY  (hidden comment: TitleBlock1-nextthing)  (graphical)
C81  104  [C0201]
C83  104  [C0201]
C90  104  [0805]
C91  104  [0805]
C92  104  [0805]
C93  104  [0805]
C94  104  [0805]
C95  104  [0805]
C96  104  [0805]
C102  104  [0805]
C103  104  [0805]
C104  104  [0805]
C105  104  [0805]
C106  104  [0805]
C109  NC  [C0201]
C190  104  [C0201]
C191  104  [C0201]
C192  104  [C0201]
C193  104  [C0201]
C194  104  [C0201]
NSR3  10K  [C0201]
NSR4  NC-0R  [C0201]
NSR5  NC-0R  [C0201]
R68  24R  [0805]
R71  240R-1%  [0805]
R90  2K-1%  [R0402]
R130  10K  [C0201]
R131  10K  [C0201]
R416  2K-1%  [R0402]
R420  24R  [0805]
R421  24R  [0805]
R422  24R  [0805]
RN20  33R*4  [RN0201]
RN21  33R*4  [RN0201]
RN22  33R*4  [RN0201]
RN23  33R*4  [RN0201]
RN24  33R*4  [RN0201]
RN25  33R*4  [RN0201]
RN26  33R*4  [RN0201]
RN27  33R*4  [RN0201]
RN28  33R*4  [RN0201]
RN29  33R*4  [RN0201]
RN30  24R*4  [RN0201]
U29  DDR3-FBGA96  [FBGA96C80P9X13]
U30  NAND FLASH X8  [TSOP-48]

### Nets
DRAM-VCC: C81.2 C90.1 C91.1 C92.1 C93.1 C94.1 C102.1 C103.1 C104.1 C105.1 C106.1 R416.2 U29.A1(VDDQ#1) U29.A8(VDDQ#6) U29.B2(VDD#3) U29.C1(VDDQ#2) U29.C9(VDDQ#9) U29.D2(VDDQ#4) U29.D9(VDD#7) U29.E9(VDDQ#8) U29.F1(VDDQ#3) U29.G7(VDD#5) U29.H2(VDDQ#5) U29.H9(VDDQ#7) U29.K2(VDD#4) U29.K8(VDD#6) U29.N1(VDD#1) U29.N9(VDD#8) U29.R1(VDD#2) U29.R9(VDD#9)
GND: C83.1 C90.2 C91.2 C92.2 C93.2 C94.2 C95.2 C96.2 C102.2 C103.2 C104.2 C105.2 C106.2 C190.1 C191.1 C192.1 C193.1 C194.1 NSR5.2 R71.1 R90.1 U29.A9(VSS#9) U29.B1(VSSQ#1) U29.B3(VSS#6) U29.B9(VSSQ#7) U29.D1(VSSQ#2) U29.D8(VSSQ#5) U29.E1(VSS#1) U29.E2(VSSQ#4) U29.E8(VSSQ#6) U29.F9(VSSQ#8) U29.G1(VSSQ#3) U29.G8(VSS#7) U29.G9(VSSQ#9) U29.J2(VSS#5) U29.J8(VSS#8) U29.L2(CS#) U29.M1(VSS#2) U29.M9(VSS#10) U29.P1(VSS#3) U29.P9(VSS#11) U29.T1(VSS#4) U29.T9(VSS#12) U30.2(NC2) U30.13(VSS1) U30.23(NC8) U30.25(NC10) U30.36(VSS2) U30.48(NC22)  [project net AGND]
VCC-3V3: C190.2 C191.2 C192.2 C193.2 NSR3.1 NSR4.1 R130.1 R131.1 U30.1(RES#) U30.12(VCC1) U30.24(NC9) U30.34(NC15) U30.37(VCC2) U30.39(NC17)  [project net HPVCC]
A0: RN27.8(R8) U29.N3(A0)
A1: RN25.6(R6) U29.P7(A1)
A2: RN28.6(R6) U29.P3(A2)
A3: RN28.5(R5) U29.N2(A3)
A4: RN25.5(R5) U29.P8(A4)
A5: RN28.7(R7) U29.P2(A5)
A6: RN25.7(R7) U29.R8(A6)
A7: RN29.7(R7) U29.R2(A7)
A8: RN25.8(R8) U29.T8(A8)
A9: RN29.5(R5) U29.R3(A9)
A10: RN24.6(R6) U29.L7(A10)
A11: RN26.5(R5) U29.R7(A11)
A12: RN24.8(R8) U29.N7(A12)
A13: RN28.8(R8) U29.T3(A13)
A14: RN26.6(R6) U29.T7(A14)
BA0: RN27.7(R7) U29.M2(BA0)
BA1: RN24.7(R7) U29.N8(BA1)
BA2: RN27.6(R6) U29.M3(BA2)
CAS: RN26.8(R8) U29.K3(CAS#)
CKE: RN24.5(R5) U29.K9(CKE)
DQ0: RN21.8(R8) U29.E3(DQL0)
DQ1: RN20.5(R5) U29.F7(DQL1)
DQ2: RN21.7(R7) U29.F2(DQL2)
DQ3: RN20.6(R6) U29.F8(DQL3)
DQ4: RN21.5(R5) U29.H3(DQL4)
DQ5: RN20.8(R8) U29.H8(DQL5)
DQ6: RN21.6(R6) U29.G2(DQL6)
DQ7: RN20.7(R7) U29.H7(DQL7)
DQ8: RN22.6(R6) U29.D7(DQU0)
DQ9: RN23.6(R6) U29.C3(DQU1)
DQ10: RN22.8(R8) U29.C8(DQU2)
DQ11: RN23.5(R5) U29.C2(DQU3)
DQ12: RN22.5(R5) U29.A7(DQU4)
DQ13: RN23.7(R7) U29.A2(DQU5)
DQ14: RN22.7(R7) U29.B8(DQU6)
DQ15: RN23.8(R8) U29.A3(DQU7)
DRAM-REF: C81.1 C83.2 C95.1 C96.1 R90.2 R416.1 U29.H1(VREFDQ) U29.M8(VREFCA)
DSCK: C109.2 R422.1 U29.J7(CK)
DSCK-N: C109.1 R68.1 U29.K7(CK#)
NALE: U30.17(ALE) ; off-sheet NALE
NCE0-N: U30.9(CE1#) ; off-sheet NCE0-N
NCE1-N: U30.10(CE2#) ; off-sheet NCE1-N
NCLE: U30.16(CLE) ; off-sheet NCLE
ND0: U30.29(IO0)
ND1: U30.30(IO1)
ND2: U30.31(IO2)
ND3: U30.32(IO3)
ND4: U30.41(IO4)
ND5: U30.42(IO5)
ND6: U30.43(IO6)
ND7: U30.44(IO7)
NDQS: U30.35(NC16) ; off-sheet NDQS
NRB0-N: R131.2 U30.7(RB1#) ; off-sheet NRB0-N
NRB1-N: R130.2 U30.6(RB2#) ; off-sheet NRB1-N
NRE-N: U30.8(RE#) ; off-sheet NRE-N
NWE-N: U30.18(WE#) ; off-sheet NWE-N
NWP-N: C194.2 NSR3.2 U30.19(WP#)
ODT: RN29.8(R8) U29.K1(ODT)
RAS: RN26.7(R7) U29.J3(RAS#)
RST: RN29.6(R6) U29.T2(RESET)
SA0: RN27.1(R1)
SA1: RN25.3(R3)
SA2: RN28.3(R3)
SA3: RN28.4(R4)
SA4: RN25.4(R4)
SA5: RN28.2(R2)
SA6: RN25.2(R2)
SA7: RN29.2(R2)
SA8: RN25.1(R1)
SA9: RN29.4(R4)
SA10: RN24.3(R3)
SA11: RN26.4(R4)
SA12: RN24.1(R1)
SA13: RN28.1(R1)
SA14: RN26.3(R3)
SBA0: RN27.2(R2)
SBA1: RN24.2(R2)
SBA2: RN27.3(R3)
SCAS: RN26.1(R1) ; off-sheet SCAS
SCK: R422.2 ; off-sheet SCK
SCK-N: R68.2 ; off-sheet SCK-N
SCKE: RN24.4(R4) ; off-sheet SCKE
SDQ0: RN21.1(R1)
SDQ1: RN20.4(R4)
SDQ2: RN21.2(R2)
SDQ3: RN20.3(R3)
SDQ4: RN21.4(R4)
SDQ5: RN20.1(R1)
SDQ6: RN21.3(R3)
SDQ7: RN20.2(R2)
SDQ8: RN22.3(R3)
SDQ9: RN23.3(R3)
SDQ10: RN22.1(R1)
SDQ11: RN23.4(R4)
SDQ12: RN22.4(R4)
SDQ13: RN23.2(R2)
SDQ14: RN22.2(R2)
SDQ15: RN23.1(R1)
SDQM0: R420.1 ; off-sheet SDQM0
SDQM1: R421.1 ; off-sheet SDQM1
SDQS0: RN30.8(R8) ; off-sheet SDQS0
SDQS0-N: RN30.7(R7) ; off-sheet SDQS0-N
SDQS1: RN30.6(R6) ; off-sheet SDQS1
SDQS1-N: RN30.5(R5) ; off-sheet SDQS1-N
SODT: RN29.1(R1) ; off-sheet SODT
SRAS: RN26.2(R2) ; off-sheet SRAS
SRST: RN29.3(R3) ; off-sheet SRST
SWE: RN27.4(R4) ; off-sheet SWE
VPS: NSR4.2 NSR5.1 U30.38(VSS3)
WE: RN27.5(R5) U29.L3(WE)
NetR71_2: R71.2 U29.L8(ZQ)
NetR420_2: R420.2 U29.E7(DML)
NetR421_2: R421.2 U29.D3(DMU)
NetRN30_1: RN30.1(R1) U29.F3(DQSL)
NetRN30_2: RN30.2(R2) U29.G3(DQSL#)
NetRN30_3: RN30.3(R3) U29.C7(DQSU)
NetRN30_4: RN30.4(R4) U29.B7(DQSU#)

Not connected (* = marked no-connect by the designer): U29 J1(NC#1) J9(NC#3) L1(NC#2) L9(NC#4) M7(A15); U30 3(NC3) 4(RB4#) 5(RB3#) 11(NC4) 14(CE3#) 15(CE4#) 20(NC5) 21(NC6) 22(NC7) 26(NC11) 27(NC12) 28(NC13) 33(NC14) 40(NC18) 45(NC19) 46(NC20) 47(NC21)

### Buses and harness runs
bus ND[7..0]
bus SA[14..0]
bus SBA[2..0]
bus SDQ[15..0]

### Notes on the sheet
- MEMORY
- DDR3
- NAND

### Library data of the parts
C81 C83 C109 = CAPACITOR_0_Dup3: PAGE: 1
C90-C96 C102-C106 = CAP_0
C190-C194 = CAPACITOR_0_Dup4: PAGE: 2
NSR3-NSR5 R130 R131 = R_Dup2
R68 R71 R420-R422 = R1 0805
R90 R416 = ?_0
RN20-RN30 = R-PACK4_1
U29 = DDR3_0
U30 = NAND_FLASH_X8

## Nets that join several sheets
AGND: 03 CPU (5 pins), 04 POWER (53 pins), 05 MISC (27 pins), 06 SDIO WIFI&BT (17 pins), 07 USB (27 pins), 08 BESIDE CPU (46 pins), 09 DDR3 (49 pins)
AVCC: 03 CPU (U1.81), 04 POWER (C25.1 U3.12 U4.1)
BAT: 04 POWER (9 pins), 05 MISC (U13.8)
CHG-IN: 04 POWER (R9.2 U3.32 U3.33), 05 MISC (U13.2)
CORE-VDD: 03 CPU (5 pins), 04 POWER (C19.1 C20.1 L4.1 U3.17), 08 BESIDE CPU (6 pins)
CPU-1V2: 03 CPU (8 pins), 04 POWER (C14.1 C15.1 L3.1 U3.10), 08 BESIDE CPU (9 pins)
DRAM-VCC: 03 CPU (7 pins), 04 POWER (5 pins), 08 BESIDE CPU (5 pins), 09 DDR3 (30 pins)
HPVCC: 03 CPU (8 pins), 04 POWER (10 pins), 05 MISC (7 pins), 06 SDIO WIFI&BT (15 pins), 07 USB (R70.2 R86.2), 08 BESIDE CPU (13 pins), 09 DDR3 (14 pins)
LDO3: 04 POWER (C28.2 C66.2 U3.11 U3.41), 06 SDIO WIFI&BT (R81.2)
LDO5: 04 POWER (C76.1 U3.19), 05 MISC (U13.7)
USBVBUS: 04 POWER (C18.1 U3.31), 07 USB (5 pins)
VBAT-EXT: 04 POWER (5 pins), 06 SDIO WIFI&BT (R80.2)
VCC-5V: 04 POWER (C77.1 D16.2 R54.2), 05 MISC (U13.3 U14.2), 07 USB (C146.1 U10.5 U15.5)
AP-EINT1: 03 CPU (U1.154), 05 MISC (U14.23)
AP-EINT2: 03 CPU (U1.155), 05 MISC (R87.1 U27.1), 06 SDIO WIFI&BT (R63.2)
AP-EINT3: 03 CPU (U1.150), 05 MISC (U14.24), 06 SDIO WIFI&BT (R62.2)
AP-WAKE-BT: 04 POWER (R11.1 U3.3), 06 SDIO WIFI&BT (U9.6)
BT-RST-N: 03 CPU (U1.104), 06 SDIO WIFI&BT (R65.1 U9.34)
BT-UART-CTS: 03 CPU (U1.15), 06 SDIO WIFI&BT (R59.2 U9.44)
BT-UART-RTS: 03 CPU (U1.14), 06 SDIO WIFI&BT (R58.2 U9.41)
BT-UART-RX: 03 CPU (U1.12), 06 SDIO WIFI&BT (R56.2 U9.43)
BT-UART-TX: 03 CPU (U1.13), 06 SDIO WIFI&BT (R55.2 U9.42)
CSI-D0: 03 CPU (U1.118), 05 MISC (RN1.2)
CSI-D1: 03 CPU (U1.119), 05 MISC (RN1.1)
CSI-D2: 03 CPU (U1.120), 05 MISC (RN1.4)
CSI-D3: 03 CPU (U1.121), 05 MISC (RN1.3)
CSI-D4: 03 CPU (U1.122), 05 MISC (RN2.2)
CSI-D5: 03 CPU (U1.123), 05 MISC (RN2.1)
CSI-D6: 03 CPU (U1.124), 05 MISC (RN2.4)
CSI-D7: 03 CPU (U1.125), 05 MISC (RN2.3)
CSI-HSYNC: 03 CPU (U1.116), 05 MISC (R40.1)
CSI-MCLK: 03 CPU (U1.115), 05 MISC (R43.2)
CSI-PCLK: 03 CPU (U1.114), 05 MISC (R41.1)
CSI-VSYNC: 03 CPU (U1.117), 05 MISC (R39.1)
DM0: 03 CPU (U1.93), 07 USB (R84.2)
DM1: 03 CPU (U1.95), 07 USB (ESD15.1 J5.2)
DP0: 03 CPU (U1.94), 07 USB (R85.2)
DP1: 03 CPU (U1.96), 07 USB (ESD18.1 J5.3)
FEL: 03 CPU (U1.157), 05 MISC (U14.7)
HPBP: 03 CPU (U1.75), 08 BESIDE CPU (C177.2 C297.2)
HPCOM: 03 CPU (U1.77), 05 MISC (U14.6)
HPL: 03 CPU (U1.74), 05 MISC (C79.1 R101.1 U14.4)
HPR: 03 CPU (U1.78), 05 MISC (C78.1 R100.1 U14.8)
LCD-CLK: 03 CPU (U1.129), 05 MISC (U13.35)
LCD-D2: 03 CPU (U1.148), 05 MISC (U13.17)
LCD-D3: 03 CPU (U1.147), 05 MISC (U13.20)
LCD-D4: 03 CPU (U1.146), 05 MISC (U13.19)
LCD-D5: 03 CPU (U1.145), 05 MISC (U13.22)
LCD-D6: 03 CPU (U1.144), 05 MISC (U13.21)
LCD-D7: 03 CPU (U1.143), 05 MISC (U13.24)
LCD-D10: 03 CPU (U1.141), 05 MISC (U13.23)
LCD-D11: 03 CPU (U1.140), 05 MISC (U13.26)
LCD-D12: 03 CPU (U1.139), 05 MISC (U13.25)
LCD-D13: 03 CPU (U1.138), 05 MISC (U13.28)
LCD-D14: 03 CPU (U1.137), 05 MISC (U13.27)
LCD-D15: 03 CPU (U1.136), 05 MISC (U13.30)
LCD-D18: 03 CPU (U1.135), 05 MISC (U13.29)
LCD-D19: 03 CPU (U1.134), 05 MISC (U13.32)
LCD-D20: 03 CPU (U1.133), 05 MISC (U13.31)
LCD-D21: 03 CPU (U1.132), 05 MISC (U13.34)
LCD-D22: 03 CPU (U1.131), 05 MISC (U13.33)
LCD-D23: 03 CPU (U1.130), 05 MISC (U13.36)
LCD-DE: 03 CPU (U1.128), 05 MISC (U13.40)
LCD-HSYNC: 03 CPU (U1.127), 05 MISC (U13.38)
LCD-VSYNC: 03 CPU (U1.126), 05 MISC (U13.37)
LRADC: 03 CPU (U1.86), 05 MISC (U14.11), 08 BESIDE CPU (C165.2)
MICIN1: 03 CPU (U1.84), 05 MISC (C54.1 U14.12)
MICM: 05 MISC (C294.2 ESD33.2 J11.5 U14.10), 08 BESIDE CPU (C164.1 R122.2)
NALE: 03 CPU (U1.7), 09 DDR3 (U30.17)
NCE0-N: 03 CPU (U1.2), 09 DDR3 (U30.9)
NCE1-N: 03 CPU (U1.3), 09 DDR3 (U30.10)
NCLE: 03 CPU (U1.6), 09 DDR3 (U30.16)
ND0: 03 CPU (U1.174), 09 DDR3 (U30.29)
ND1: 03 CPU (U1.172), 09 DDR3 (U30.30)
ND2: 03 CPU (U1.171), 09 DDR3 (U30.31)
ND3: 03 CPU (U1.170), 09 DDR3 (U30.32)
ND4: 03 CPU (U1.168), 09 DDR3 (U30.41)
ND5: 03 CPU (U1.167), 09 DDR3 (U30.42)
ND6: 03 CPU (U1.166), 09 DDR3 (U30.43)
ND7: 03 CPU (U1.165), 09 DDR3 (U30.44)
NDQS: 03 CPU (U1.162), 09 DDR3 (U30.35)
NMI: 03 CPU (U1.158), 04 POWER (R16.1 U3.48)
NRB0-N: 03 CPU (U1.176), 09 DDR3 (R131.2 U30.7)
NRB1-N: 03 CPU (U1.175), 09 DDR3 (R130.2 U30.6)
NRE-N: 03 CPU (U1.1), 09 DDR3 (U30.8)
NWE-N: 03 CPU (U1.8), 09 DDR3 (U30.18)
OSC24MI: 03 CPU (U1.92), 08 BESIDE CPU (C1.2 X1.1)
OSC24MO: 03 CPU (U1.91), 08 BESIDE CPU (C5.2 X1.3)
PB0: 03 CPU (U1.101), 04 POWER (U3.2), 08 BESIDE CPU (R4.2)
PB1: 03 CPU (U1.102), 04 POWER (U3.1), 08 BESIDE CPU (R1.2)
PB2: 03 CPU (U1.103), 05 MISC (U13.18)
PB10: 03 CPU (U1.10), 04 POWER (U3.6), 07 USB (R74.2 U10.4)
PB15: 03 CPU (U1.105), 05 MISC (U13.11), 08 BESIDE CPU (R3.2)
PB16: 03 CPU (U1.106), 05 MISC (U13.9), 08 BESIDE CPU (R2.2)
PB17: 03 CPU (U1.161), 05 MISC (U14.26 U27.2), 08 BESIDE CPU (R6.2)
PB18: 03 CPU (U1.160), 05 MISC (U14.25 U27.4), 08 BESIDE CPU (R18.2)
PF0: 03 CPU (U1.107), 06 SDIO WIFI&BT (R48.2 U9.19)
PF1: 03 CPU (U1.108), 06 SDIO WIFI&BT (R49.2 U9.18)
PF2: 03 CPU (U1.110), 06 SDIO WIFI&BT (R50.2 U9.17)
PF3: 03 CPU (U1.111), 06 SDIO WIFI&BT (R51.2 U9.16)
PF4: 03 CPU (U1.112), 06 SDIO WIFI&BT (R52.2 U9.15)
PF5: 03 CPU (U1.113), 06 SDIO WIFI&BT (R53.2 U9.14)
PG2: 03 CPU (U1.153), 07 USB (ESD11.1 J4.4 R70.1 TP18.1)
PG3: 03 CPU (U1.152), 05 MISC (U14.3)
PMU-GPIO1: 04 POWER (U3.18), 05 MISC (R414.1 TP7.1)
POWER-ON: 04 POWER (R83.2 SW1.2), 05 MISC (U13.10)
RESET: 03 CPU (U1.159), 04 POWER (C37.2 R17.1 U3.25), 08 BESIDE CPU (C166.2)
SA0: 03 CPU (U1.64), 09 DDR3 (RN27.1)
SA1: 03 CPU (U1.52), 09 DDR3 (RN25.3)
SA2: 03 CPU (U1.66), 09 DDR3 (RN28.3)
SA3: 03 CPU (U1.65), 09 DDR3 (RN28.4)
SA4: 03 CPU (U1.51), 09 DDR3 (RN25.4)
SA5: 03 CPU (U1.67), 09 DDR3 (RN28.2)
SA6: 03 CPU (U1.54), 09 DDR3 (RN25.2)
SA7: 03 CPU (U1.71), 09 DDR3 (RN29.2)
SA8: 03 CPU (U1.55), 09 DDR3 (RN25.1)
SA9: 03 CPU (U1.69), 09 DDR3 (RN29.4)
SA10: 03 CPU (U1.48), 09 DDR3 (RN24.3)
SA11: 03 CPU (U1.56), 09 DDR3 (RN26.4)
SA12: 03 CPU (U1.50), 09 DDR3 (RN24.1)
SA13: 03 CPU (U1.68), 09 DDR3 (RN28.1)
SA14: 03 CPU (U1.57), 09 DDR3 (RN26.3)
SBA0: 03 CPU (U1.63), 09 DDR3 (RN27.2)
SBA1: 03 CPU (U1.49), 09 DDR3 (RN24.2)
SBA2: 03 CPU (U1.61), 09 DDR3 (RN27.3)
SCAS: 03 CPU (U1.59), 09 DDR3 (RN26.1)
SCK: 03 CPU (U1.45), 09 DDR3 (R422.2)
SCK-N: 03 CPU (U1.46), 09 DDR3 (R68.2)
SCKE: 03 CPU (U1.47), 09 DDR3 (RN24.4)
SDQ0: 03 CPU (U1.22), 09 DDR3 (RN21.1)
SDQ1: 03 CPU (U1.40), 09 DDR3 (RN20.4)
SDQ2: 03 CPU (U1.21), 09 DDR3 (RN21.2)
SDQ3: 03 CPU (U1.41), 09 DDR3 (RN20.3)
SDQ4: 03 CPU (U1.19), 09 DDR3 (RN21.4)
SDQ5: 03 CPU (U1.44), 09 DDR3 (RN20.1)
SDQ6: 03 CPU (U1.20), 09 DDR3 (RN21.3)
SDQ7: 03 CPU (U1.42), 09 DDR3 (RN20.2)
SDQ8: 03 CPU (U1.37), 09 DDR3 (RN22.3)
SDQ9: 03 CPU (U1.25), 09 DDR3 (RN23.3)
SDQ10: 03 CPU (U1.39), 09 DDR3 (RN22.1)
SDQ11: 03 CPU (U1.24), 09 DDR3 (RN23.4)
SDQ12: 03 CPU (U1.36), 09 DDR3 (RN22.4)
SDQ13: 03 CPU (U1.26), 09 DDR3 (RN23.2)
SDQ14: 03 CPU (U1.38), 09 DDR3 (RN22.2)
SDQ15: 03 CPU (U1.27), 09 DDR3 (RN23.1)
SDQM0: 03 CPU (U1.29), 09 DDR3 (R420.1)
SDQM1: 03 CPU (U1.28), 09 DDR3 (R421.1)
SDQS0: 03 CPU (U1.31), 09 DDR3 (RN30.8)
SDQS0-N: 03 CPU (U1.32), 09 DDR3 (RN30.7)
SDQS1: 03 CPU (U1.33), 09 DDR3 (RN30.6)
SDQS1-N: 03 CPU (U1.34), 09 DDR3 (RN30.5)
SODT: 03 CPU (U1.72), 09 DDR3 (RN29.1)
SRAS: 03 CPU (U1.58), 09 DDR3 (RN26.2)
SRST: 03 CPU (U1.70), 09 DDR3 (RN29.3)
SVREF: 03 CPU (5 pins), 08 BESIDE CPU (C295.2)
SWE: 03 CPU (U1.60), 09 DDR3 (RN27.4)
TPX1: 03 CPU (U1.89), 05 MISC (U13.13), 08 BESIDE CPU (C173.2)
TPX2: 03 CPU (U1.87), 05 MISC (U13.14), 08 BESIDE CPU (C174.2)
TPY1: 03 CPU (U1.90), 05 MISC (U13.15), 08 BESIDE CPU (C175.2)
TPY2: 03 CPU (U1.88), 05 MISC (U13.16), 08 BESIDE CPU (C176.2)
TS: 04 POWER (R12.2 U3.37), 05 MISC (U13.6)
TVOUT: 03 CPU (U1.99), 05 MISC (C53.1 C55.2 L9.1 R60.1)
UART1-RX: 03 CPU (Q11.3), 05 MISC (U14.5)
VMIC: 03 CPU (U1.85), 05 MISC (R113.2 TP4.1)
VRA1: 03 CPU (U1.83), 08 BESIDE CPU (C164.2)
VRA2: 03 CPU (U1.82), 08 BESIDE CPU (C169.2 C170.2 R121.2)
VRP: 03 CPU (U1.80), 08 BESIDE CPU (C167.2 C168.2)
